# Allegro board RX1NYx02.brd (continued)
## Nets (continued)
GND_BD1: C1.2 C2.1 C3.1 C4.1 C5.1 C6.2 C7.2 C8.1 C9.1 C10.2 C13.1 C15.1 C16.2 C20.1 C145.1 C146.1 C147.1 C148.1 C149.1 C163.1 C166.2 DS_BD1_PWR.2(C) MH1.1 MH2.1 P1.2 P2.2 P3.2 P13.2 P_BD1_CLK0_N.2 P_BD1_CLK0_N.3 P_BD1_CLK0_N.4 P_BD1_CLK0_N.5 P_BD1_CLK0_N.6 P_BD1_CLK0_P.2 P_BD1_CLK0_P.3 P_BD1_CLK0_P.4 P_BD1_CLK0_P.5 P_BD1_CLK0_P.6 P_BD1_CLK1_N.2 P_BD1_CLK1_N.3 P_BD1_CLK1_N.4 P_BD1_CLK1_N.5 P_BD1_CLK1_N.6(MH6) P_BD1_CLK1_P.2 P_BD1_CLK1_P.3 P_BD1_CLK1_P.4 P_BD1_CLK1_P.5 P_BD1_CLK1_P.6(MH6) P_BD1_CLK2_N.2 P_BD1_CLK2_N.3 P_BD1_CLK2_N.4 P_BD1_CLK2_N.5 P_BD1_CLK2_N.6 P_BD1_CLK2_P.2 P_BD1_CLK2_P.3 P_BD1_CLK2_P.4 P_BD1_CLK2_P.5 P_BD1_CLK2_P.6 P_BD1_CLK3_N.2 P_BD1_CLK3_N.3 P_BD1_CLK3_N.4 P_BD1_CLK3_N.5 P_BD1_CLK3_N.6(MH6) P_BD1_CLK3_P.2 P_BD1_CLK3_P.3 P_BD1_CLK3_P.4 P_BD1_CLK3_P.5 P_BD1_CLK3_P.6(MH6) P_BD1_CMTS_N.2 P_BD1_CMTS_N.3 P_BD1_CMTS_N.4 P_BD1_CMTS_N.5 P_BD1_CMTS_N.6 P_BD1_CMTS_P.2 P_BD1_CMTS_P.3 P_BD1_CMTS_P.4 P_BD1_CMTS_P.5 P_BD1_CMTS_P.6 P_BD1_TRIG_IN_N.2 P_BD1_TRIG_IN_N.3 P_BD1_TRIG_IN_N.4 P_BD1_TRIG_IN_N.5 P_BD1_TRIG_IN_N.6(MH6) P_BD1_TRIG_IN_P.2 P_BD1_TRIG_IN_P.3 P_BD1_TRIG_IN_P.4 P_BD1_TRIG_IN_P.5 P_BD1_TRIG_IN_P.6(MH6) P_CPU_OCP_0_N.2 P_CPU_OCP_0_N.3 P_CPU_OCP_0_N.4 P_CPU_OCP_0_N.5 P_CPU_OCP_0_N.6 P_CPU_OCP_0_P.2 P_CPU_OCP_0_P.3 P_CPU_OCP_0_P.4 P_CPU_OCP_0_P.5 P_CPU_OCP_0_P.6 P_CPU_OCP_1_N.2 P_CPU_OCP_1_N.3 P_CPU_OCP_1_N.4 P_CPU_OCP_1_N.5 P_CPU_OCP_1_N.6 P_CPU_OCP_1_P.2 P_CPU_OCP_1_P.3 P_CPU_OCP_1_P.4 P_CPU_OCP_1_P.5 P_CPU_OCP_1_P.6 P_CPU_OCP_2_N.2 P_CPU_OCP_2_N.3 P_CPU_OCP_2_N.4 P_CPU_OCP_2_N.5 P_CPU_OCP_2_N.6 P_CPU_OCP_2_P.2 P_CPU_OCP_2_P.3 P_CPU_OCP_2_P.4 P_CPU_OCP_2_P.5 P_CPU_OCP_2_P.6 P_CPU_OCP_3_N.2 P_CPU_OCP_3_N.3 P_CPU_OCP_3_N.4 P_CPU_OCP_3_N.5 P_CPU_OCP_3_N.6 P_CPU_OCP_3_P.2 P_CPU_OCP_3_P.3 P_CPU_OCP_3_P.4 P_CPU_OCP_3_P.5 P_CPU_OCP_3_P.6 P_CPU_OCP_4_N.2 P_CPU_OCP_4_N.3 P_CPU_OCP_4_N.4 P_CPU_OCP_4_N.5 P_CPU_OCP_4_N.6 P_CPU_OCP_4_P.2 P_CPU_OCP_4_P.3 P_CPU_OCP_4_P.4 P_CPU_OCP_4_P.5 P_CPU_OCP_4_P.6 P_CPU_OCP_5_N.2 P_CPU_OCP_5_N.3 P_CPU_OCP_5_N.4 P_CPU_OCP_5_N.5 P_CPU_OCP_5_N.6 P_CPU_OCP_5_P.2 P_CPU_OCP_5_P.3 P_CPU_OCP_5_P.4 P_CPU_OCP_5_P.5 P_CPU_OCP_5_P.6 P_CPU_OCP_6_N.2 P_CPU_OCP_6_N.3 P_CPU_OCP_6_N.4 P_CPU_OCP_6_N.5 P_CPU_OCP_6_N.6 P_CPU_OCP_6_P.2 P_CPU_OCP_6_P.3 P_CPU_OCP_6_P.4 P_CPU_OCP_6_P.5 P_CPU_OCP_6_P.6 P_CPU_OCP_7_N.2 P_CPU_OCP_7_N.3 P_CPU_OCP_7_N.4 P_CPU_OCP_7_N.5 P_CPU_OCP_7_N.6 P_CPU_OCP_7_P.2 P_CPU_OCP_7_P.3 P_CPU_OCP_7_P.4 P_CPU_OCP_7_P.5 P_CPU_OCP_7_P.6 P_OCP1.A1 P_OCP1.A2 P_OCP1.A3 P_OCP1.A4 P_OCP1.A5 P_OCP1.A6 P_OCP1.A13 P_OCP1.A16 P_OCP1.A19 P_OCP1.A22 P_OCP1.A25 P_OCP1.A28 P_OCP1.A29 P_OCP1.A32 P_OCP1.A35 P_OCP1.A38 P_OCP1.A41 P_OCP1.A43 P_OCP1.A46 P_OCP1.A49 P_OCP1.A52 P_OCP1.A55 P_OCP1.A58 P_OCP1.A61 P_OCP1.A64 P_OCP1.A67 P_OCP1.B13 P_OCP1.B16 P_OCP1.B19 P_OCP1.B22 P_OCP1.B25 P_OCP1.B28 P_OCP1.B29 P_OCP1.B32 P_OCP1.B35 P_OCP1.B38 P_OCP1.B41 P_OCP1.B43 P_OCP1.B46 P_OCP1.B49 P_OCP1.B52 P_OCP1.B55 P_OCP1.B58 P_OCP1.B61 P_OCP1.B64 P_OCP1.B67 P_OCP1.OCP_A10 P_OCP1.OCP_A13 P_OCP1.OCP_B10 P_OCP1.OCP_B13 P_OCP_CPU_0_N.2 P_OCP_CPU_0_N.3 P_OCP_CPU_0_N.4 P_OCP_CPU_0_N.5 P_OCP_CPU_0_N.6(MH6) P_OCP_CPU_0_P.2 P_OCP_CPU_0_P.3 P_OCP_CPU_0_P.4 P_OCP_CPU_0_P.5 P_OCP_CPU_0_P.6(MH6) P_OCP_CPU_1_N.2 P_OCP_CPU_1_N.3 P_OCP_CPU_1_N.4 P_OCP_CPU_1_N.5 P_OCP_CPU_1_N.6(MH6) P_OCP_CPU_1_P.2 P_OCP_CPU_1_P.3 P_OCP_CPU_1_P.4 P_OCP_CPU_1_P.5 P_OCP_CPU_1_P.6(MH6) P_OCP_CPU_2_N.2 P_OCP_CPU_2_N.3 P_OCP_CPU_2_N.4 P_OCP_CPU_2_N.5 P_OCP_CPU_2_N.6(MH6) P_OCP_CPU_2_P.2 P_OCP_CPU_2_P.3 P_OCP_CPU_2_P.4 P_OCP_CPU_2_P.5 P_OCP_CPU_2_P.6(MH6) P_OCP_CPU_3_N.2 P_OCP_CPU_3_N.3 P_OCP_CPU_3_N.4 P_OCP_CPU_3_N.5 P_OCP_CPU_3_N.6(MH6) P_OCP_CPU_3_P.2 P_OCP_CPU_3_P.3 P_OCP_CPU_3_P.4 P_OCP_CPU_3_P.5 P_OCP_CPU_3_P.6(MH6) P_OCP_CPU_4_N.2 P_OCP_CPU_4_N.3 P_OCP_CPU_4_N.4 P_OCP_CPU_4_N.5 P_OCP_CPU_4_N.6(MH6) P_OCP_CPU_4_P.2 P_OCP_CPU_4_P.3 P_OCP_CPU_4_P.4 P_OCP_CPU_4_P.5 P_OCP_CPU_4_P.6(MH6) P_OCP_CPU_5_N.2 P_OCP_CPU_5_N.3 P_OCP_CPU_5_N.4 P_OCP_CPU_5_N.5 P_OCP_CPU_5_N.6(MH6) P_OCP_CPU_5_P.2 P_OCP_CPU_5_P.3 P_OCP_CPU_5_P.4 P_OCP_CPU_5_P.5 P_OCP_CPU_5_P.6(MH6) P_OCP_CPU_6_N.2 P_OCP_CPU_6_N.3 P_OCP_CPU_6_N.4 P_OCP_CPU_6_N.5 P_OCP_CPU_6_N.6(MH6) P_OCP_CPU_6_P.2 P_OCP_CPU_6_P.3 P_OCP_CPU_6_P.4 P_OCP_CPU_6_P.5 P_OCP_CPU_6_P.6(MH6) P_OCP_CPU_7_N.2 P_OCP_CPU_7_N.3 P_OCP_CPU_7_N.4 P_OCP_CPU_7_N.5 P_OCP_CPU_7_N.6(MH6) P_OCP_CPU_7_P.2 P_OCP_CPU_7_P.3 P_OCP_CPU_7_P.4 P_OCP_CPU_7_P.5 P_OCP_CPU_7_P.6(MH6) Q1.2(S) SW1.2 U1.3 U2.3 U3.3 U4.1 U5.3 U6.3 U7.3 U24.9 U24.17 U26.3
GND_BD2: BD2_P_OCP_CPU_0_N.2 BD2_P_OCP_CPU_0_N.3 BD2_P_OCP_CPU_0_N.4 BD2_P_OCP_CPU_0_N.5 BD2_P_OCP_CPU_0_N.6(MH6) BD2_P_OCP_CPU_0_P.2 BD2_P_OCP_CPU_0_P.3 BD2_P_OCP_CPU_0_P.4 BD2_P_OCP_CPU_0_P.5 BD2_P_OCP_CPU_0_P.6(MH6) C73.2 C74.1 C75.2 C76.1 C77.1 C78.1 C79.1 C80.2 C81.2 C82.1 C83.1 C84.2 C85.2 C87.1 C88.2 C89.1 C155.1 C156.1 C158.1 C165.1 C167.2 DS_BD2_PWR.2(C) MH5.1 MH6.1 P7.2 P8.2 P9.2 P15.2 P_BD2_CLK0_N.2 P_BD2_CLK0_N.3 P_BD2_CLK0_N.4 P_BD2_CLK0_N.5 P_BD2_CLK0_N.6 P_BD2_CLK0_P.2 P_BD2_CLK0_P.3 P_BD2_CLK0_P.4 P_BD2_CLK0_P.5 P_BD2_CLK0_P.6 P_BD2_CLK1_N.2 P_BD2_CLK1_N.3 P_BD2_CLK1_N.4 P_BD2_CLK1_N.5 P_BD2_CLK1_N.6(MH6) P_BD2_CLK1_P.2 P_BD2_CLK1_P.3 P_BD2_CLK1_P.4 P_BD2_CLK1_P.5 P_BD2_CLK1_P.6(MH6) P_BD2_CLK2_N.2 P_BD2_CLK2_N.3 P_BD2_CLK2_N.4 P_BD2_CLK2_N.5 P_BD2_CLK2_N.6 P_BD2_CLK2_P.2 P_BD2_CLK2_P.3 P_BD2_CLK2_P.4 P_BD2_CLK2_P.5 P_BD2_CLK2_P.6 P_BD2_CMTS_N.2 P_BD2_CMTS_N.3 P_BD2_CMTS_N.4 P_BD2_CMTS_N.5 P_BD2_CMTS_N.6 P_BD2_CMTS_P.2 P_BD2_CMTS_P.3 P_BD2_CMTS_P.4 P_BD2_CMTS_P.5 P_BD2_CMTS_P.6 P_BD2_TRIG_IN_N.2 P_BD2_TRIG_IN_N.3 P_BD2_TRIG_IN_N.4 P_BD2_TRIG_IN_N.5 P_BD2_TRIG_IN_N.6(MH6) P_BD2_TRIG_IN_P.2 P_BD2_TRIG_IN_P.3 P_BD2_TRIG_IN_P.4 P_BD2_TRIG_IN_P.5 P_BD2_TRIG_IN_P.6(MH6) P_CPU_OCP_8_N.2 P_CPU_OCP_8_N.3 P_CPU_OCP_8_N.4 P_CPU_OCP_8_N.5 P_CPU_OCP_8_N.6 P_CPU_OCP_8_P.2 P_CPU_OCP_8_P.3 P_CPU_OCP_8_P.4 P_CPU_OCP_8_P.5 P_CPU_OCP_8_P.6 P_CPU_OCP_9_N.2 P_CPU_OCP_9_N.3 P_CPU_OCP_9_N.4 P_CPU_OCP_9_N.5 P_CPU_OCP_9_N.6 P_CPU_OCP_9_P.2 P_CPU_OCP_9_P.3 P_CPU_OCP_9_P.4 P_CPU_OCP_9_P.5 P_CPU_OCP_9_P.6 P_CPU_OCP_10_N.2 P_CPU_OCP_10_N.3 P_CPU_OCP_10_N.4 P_CPU_OCP_10_N.5 P_CPU_OCP_10_N.6 P_CPU_OCP_10_P.2 P_CPU_OCP_10_P.3 P_CPU_OCP_10_P.4 P_CPU_OCP_10_P.5 P_CPU_OCP_10_P.6 P_CPU_OCP_11_N.2 P_CPU_OCP_11_N.3 P_CPU_OCP_11_N.4 P_CPU_OCP_11_N.5 P_CPU_OCP_11_N.6 P_CPU_OCP_11_P.2 P_CPU_OCP_11_P.3 P_CPU_OCP_11_P.4 P_CPU_OCP_11_P.5 P_CPU_OCP_11_P.6 P_CPU_OCP_12_N.2 P_CPU_OCP_12_N.3 P_CPU_OCP_12_N.4 P_CPU_OCP_12_N.5 P_CPU_OCP_12_N.6 P_CPU_OCP_12_P.2 P_CPU_OCP_12_P.3 P_CPU_OCP_12_P.4 P_CPU_OCP_12_P.5 P_CPU_OCP_12_P.6 P_CPU_OCP_13_N.2 P_CPU_OCP_13_N.3 P_CPU_OCP_13_N.4 P_CPU_OCP_13_N.5 P_CPU_OCP_13_N.6 P_CPU_OCP_13_P.2 P_CPU_OCP_13_P.3 P_CPU_OCP_13_P.4 P_CPU_OCP_13_P.5 P_CPU_OCP_13_P.6 P_CPU_OCP_14_N.2 P_CPU_OCP_14_N.3 P_CPU_OCP_14_N.4 P_CPU_OCP_14_N.5 P_CPU_OCP_14_N.6 P_CPU_OCP_14_P.2 P_CPU_OCP_14_P.3 P_CPU_OCP_14_P.4 P_CPU_OCP_14_P.5 P_CPU_OCP_14_P.6 P_CPU_OCP_15_N.2 P_CPU_OCP_15_N.3 P_CPU_OCP_15_N.4 P_CPU_OCP_15_N.5 P_CPU_OCP_15_N.6 P_CPU_OCP_15_P.2 P_CPU_OCP_15_P.3 P_CPU_OCP_15_P.4 P_CPU_OCP_15_P.5 P_CPU_OCP_15_P.6 P_OCP2.A1 P_OCP2.A2 P_OCP2.A3 P_OCP2.A4 P_OCP2.A5 P_OCP2.A6 P_OCP2.A13 P_OCP2.A16 P_OCP2.A19 P_OCP2.A22 P_OCP2.A25 P_OCP2.A28 P_OCP2.A29 P_OCP2.A32 P_OCP2.A35 P_OCP2.A38 P_OCP2.A41 P_OCP2.A43 P_OCP2.A46 P_OCP2.A49 P_OCP2.A52 P_OCP2.A55 P_OCP2.A58 P_OCP2.A61 P_OCP2.A64 P_OCP2.A67 P_OCP2.B13 P_OCP2.B16 P_OCP2.B19 P_OCP2.B22 P_OCP2.B25 P_OCP2.B28 P_OCP2.B29 P_OCP2.B32 P_OCP2.B35 P_OCP2.B38 P_OCP2.B41 P_OCP2.B43 P_OCP2.B46 P_OCP2.B49 P_OCP2.B52 P_OCP2.B55 P_OCP2.B58 P_OCP2.B61 P_OCP2.B64 P_OCP2.B67 P_OCP2.OCP_A10 P_OCP2.OCP_A13 P_OCP2.OCP_B10 P_OCP2.OCP_B13 P_OCP_CPU_8_N.2 P_OCP_CPU_8_N.3 P_OCP_CPU_8_N.4 P_OCP_CPU_8_N.5 P_OCP_CPU_8_N.6(MH6) P_OCP_CPU_8_P.2 P_OCP_CPU_8_P.3 P_OCP_CPU_8_P.4 P_OCP_CPU_8_P.5 P_OCP_CPU_8_P.6(MH6) P_OCP_CPU_9_N.2 P_OCP_CPU_9_N.3 P_OCP_CPU_9_N.4 P_OCP_CPU_9_N.5 P_OCP_CPU_9_N.6(MH6) P_OCP_CPU_9_P.2 P_OCP_CPU_9_P.3 P_OCP_CPU_9_P.4 P_OCP_CPU_9_P.5 P_OCP_CPU_9_P.6(MH6) P_OCP_CPU_10_N.2 P_OCP_CPU_10_N.3 P_OCP_CPU_10_N.4 P_OCP_CPU_10_N.5 P_OCP_CPU_10_N.6(MH6) P_OCP_CPU_10_P.2 P_OCP_CPU_10_P.3 P_OCP_CPU_10_P.4 P_OCP_CPU_10_P.5 P_OCP_CPU_10_P.6(MH6) P_OCP_CPU_11_N.2 P_OCP_CPU_11_N.3 P_OCP_CPU_11_N.4 P_OCP_CPU_11_N.5 P_OCP_CPU_11_N.6(MH6) P_OCP_CPU_11_P.2 P_OCP_CPU_11_P.3 P_OCP_CPU_11_P.4 P_OCP_CPU_11_P.5 P_OCP_CPU_11_P.6(MH6) P_OCP_CPU_12_N.2 P_OCP_CPU_12_N.3 P_OCP_CPU_12_N.4 P_OCP_CPU_12_N.5 P_OCP_CPU_12_N.6(MH6) P_OCP_CPU_12_P.2 P_OCP_CPU_12_P.3 P_OCP_CPU_12_P.4 P_OCP_CPU_12_P.5 P_OCP_CPU_12_P.6(MH6) P_OCP_CPU_13_N.2 P_OCP_CPU_13_N.3 P_OCP_CPU_13_N.4 P_OCP_CPU_13_N.5 P_OCP_CPU_13_N.6(MH6) P_OCP_CPU_13_P.2 P_OCP_CPU_13_P.3 P_OCP_CPU_13_P.4 P_OCP_CPU_13_P.5 P_OCP_CPU_13_P.6(MH6) P_OCP_CPU_14_N.2 P_OCP_CPU_14_N.3 P_OCP_CPU_14_N.4 P_OCP_CPU_14_N.5 P_OCP_CPU_14_N.6(MH6) P_OCP_CPU_14_P.2 P_OCP_CPU_14_P.3 P_OCP_CPU_14_P.4 P_OCP_CPU_14_P.5 P_OCP_CPU_14_P.6(MH6) P_OCP_CPU_15_N.2 P_OCP_CPU_15_N.3 P_OCP_CPU_15_N.4 P_OCP_CPU_15_N.5 P_OCP_CPU_15_N.6(MH6) P_OCP_CPU_15_P.2 P_OCP_CPU_15_P.3 P_OCP_CPU_15_P.4 P_OCP_CPU_15_P.5 P_OCP_CPU_15_P.6(MH6) Q3.2(S) SW3.2 U17.3 U18.3 U19.3 U20.1 U21.3 U22.3 U23.3 U25.9 U25.17 U27.3
GND_SIGNAL: J_S2D_BOT.1(GND) J_S2D_TOP.1(GND) Z_42.5_BOT.1 Z_42.5_BOT.3(RY) Z_42.5_BOT_END.1 Z_42.5_BOT_END.3 Z_42.5_TOP.1 Z_42.5_TOP.3(RY) Z_42.5_TOP_END.1 Z_42.5_TOP_END.3 Z_85D_BOT.1 Z_85D_BOT.3(RY) Z_85D_BOT_END.1 Z_85D_BOT_END.4 Z_85D_TOP.1 Z_85D_TOP.3(RY) Z_85D_TOP_END.1 Z_85D_TOP_END.4 Z_100D_BOT.1 Z_100D_BOT.3(RY) Z_100D_BOT_END.1 Z_100D_BOT_END.4 Z_100D_TOP.1 Z_100D_TOP.3(RY) Z_100D_TOP_END.1 Z_100D_TOP_END.4
BD1_555_DISCHARGE: C6.1 R11.1 R13.1 U4.6 U4.7
BD1_555_OUT: R16.2 R18.2 U4.3
BD1_555_OUT_JP: P3.1 R16.1
BD1_555_RST_N: C7.1 R15.1 U4.4
BD1_555_TRI: R8.2 R14.2 U4.2
BD1_AUX_PWR_EN: P_OCP1.B12 TP26.TEST
BD1_BIF0_N: P_OCP1.B7 TP18.TEST
BD1_BIF1_N: P_OCP1.B8 TP20.TEST
BD1_BIF2_N: P_OCP1.B9 TP22.TEST
BD1_BTN_NC: R7.1 R9.1 SW1.1 U1.1
BD1_BTN_NO: R8.1 R17.1 SW1.3 U6.2
BD1_BUS_SEL: C163.2 P13.1 Q1.1 R7.2 R18.1 R158.1 U26.2
BD1_CLK_NCSI: P_OCP1.OCP_A14 TP17.TEST
BD1_MAIN_PWR_EN: P_OCP1.OCP_B2 TP27.TEST
BD1_NCSI_ARBIN: P_OCP1.OCP_A4 TP8.TEST
BD1_NCSI_ARBOUT: P_OCP1.OCP_A5 TP9.TEST
BD1_NCSI_CRS_DV: P_OCP1.OCP_B14 TP16.TEST
BD1_NCSI_RXD0: P_OCP1.OCP_B9 TP14.TEST
BD1_NCSI_RXD1: P_OCP1.OCP_B8 TP12.TEST
BD1_NCSI_TXD0: P_OCP1.OCP_A9 TP15.TEST
BD1_NCSI_TXD1: P_OCP1.OCP_A8 TP13.TEST
BD1_NCSI_TXEN: P_OCP1.OCP_A7 TP11.TEST
BD1_NIC_PWR_GOOD: P_OCP1.OCP_B1 R5.1
BD1_PERST0_N: P_OCP1.B10 TP24.TEST
BD1_PERST1_N: P_OCP1.A11 TP25.TEST
BD1_PERST2_N: P_OCP1.OCP_A1 TP3.TEST
BD1_PERST3_N: P_OCP1.OCP_A2 TP4.TEST
BD1_PRSNTA_N: P_OCP1.A10 R1.2 R2.2 R3.2 R6.2
BD1_PRSNTB0_N: P_OCP1.B42 R1.1
BD1_PRSNTB1_N: P_OCP1.A42 R2.1
BD1_PRSNTB2_N: P_OCP1.A12 R3.1
BD1_PRSNTB3_N: P_OCP1.B70 R6.1
BD1_PWRBRK_N: P_OCP1.A70 R164.1
BD1_REFCLK0_DN: P_BD1_CLK0_N.1 P_OCP1.B14
BD1_REFCLK0_DP: P_BD1_CLK0_P.1 P_OCP1.B15
BD1_REFCLK1_DN: P_BD1_CLK1_N.1 P_OCP1.A14
BD1_REFCLK1_DP: P_BD1_CLK1_P.1 P_OCP1.A15
BD1_REFCLK2_DN: P_BD1_CLK2_N.1 P_OCP1.OCP_B11
BD1_REFCLK2_DP: P_BD1_CLK2_P.1 P_OCP1.OCP_B12
BD1_REFCLK3_DN: P_BD1_CLK3_N.1 P_OCP1.OCP_A11
BD1_REFCLK3_DP: P_BD1_CLK3_P.1 P_OCP1.OCP_A12
BD1_SCAN_CLK: P_OCP1.OCP_B6 TP1.TEST
BD1_SCAN_DATA_IN: P_OCP1.OCP_B4 TP7.TEST
BD1_SCAN_DATA_OUT: P_OCP1.OCP_B5 TP10.TEST
BD1_SCAN_LD_N: P_OCP1.OCP_B3 TP5.TEST
BD1_SLOT_ID: P_OCP1.OCP_B7 TP2.TEST
BD1_SMB_CLK: P_OCP1.A7 TP19.TEST
BD1_SMB_RST_N: P_OCP1.A9 TP23.TEST
BD1_SMB_SDA: P_OCP1.A8 TP21.TEST
BD1_WAKE_N: P_OCP1.OCP_A3 TP6.TEST
BD2_555_DISCHARGE: C80.1 R88.1 R89.1 U20.6 U20.7
BD2_555_OUT: R93.2 R95.2 U20.3
BD2_555_OUT_JP: P9.1 R93.1
BD2_555_RST_N: C81.1 R92.1 U20.4
BD2_555_TRI: R85.2 R91.2 U20.2
BD2_AUX_PWR_EN: P_OCP2.B12 TP81.TEST
BD2_BIF0_N: P_OCP2.B7 TP72.TEST
BD2_BIF1_N: P_OCP2.B8 TP73.TEST
BD2_BIF2_N: P_OCP2.B9 TP77.TEST
BD2_BTN_NC: R84.1 R86.1 SW3.1 U17.1
BD2_BTN_NO: R85.1 R94.1 SW3.3 U22.2
BD2_BUS_SEL: C165.2 P15.1 Q3.1 R84.2 R95.1 R160.1 U27.2
BD2_CLK_NCSI: P_OCP2.OCP_A14 TP71.TEST
BD2_MAIN_PWR_EN: P_OCP2.OCP_B2 TP56.TEST
BD2_NCSI_ARBIN: P_OCP2.OCP_A4 TP74.TEST
BD2_NCSI_ARBOUT: P_OCP2.OCP_A5 TP62.TEST
BD2_NCSI_CRS_DV: P_OCP2.OCP_B14 TP70.TEST
BD2_NCSI_RXD0: P_OCP2.OCP_B9 TP68.TEST
BD2_NCSI_RXD1: P_OCP2.OCP_B8 TP66.TEST
BD2_NCSI_TXD0: P_OCP2.OCP_A9 TP69.TEST
BD2_NCSI_TXD1: P_OCP2.OCP_A8 TP67.TEST
BD2_NCSI_TXEN: P_OCP2.OCP_A7 TP65.TEST
BD2_NIC_PWR_GOOD: P_OCP2.OCP_B1 R79.1
BD2_PE_OCP_CPU_0_DN: BD2_P_OCP_CPU_0_N.1 P_OCP2.A17
BD2_PE_OCP_CPU_0_DP: BD2_P_OCP_CPU_0_P.1 P_OCP2.A18
BD2_PERST0_N: P_OCP2.B10 TP79.TEST
BD2_PERST1_N: P_OCP2.A11 TP80.TEST
BD2_PERST2_N: P_OCP2.OCP_A1 TP55.TEST
BD2_PERST3_N: P_OCP2.OCP_A2 TP57.TEST
BD2_PRSNTA_N: P_OCP2.A10 R78.2 R80.2 R81.2 R82.2
BD2_PRSNTB0_N: P_OCP2.B42 R78.1
BD2_PRSNTB1_N: P_OCP2.A42 R80.1
BD2_PRSNTB2_N: P_OCP2.A12 R81.1
BD2_PRSNTB3_N: P_OCP2.B70 R82.1
BD2_PWRBRK_N: P_OCP2.A70 R166.1
BD2_REFCLK0_DN: P_BD2_CLK0_N.1 P_OCP2.B14
BD2_REFCLK0_DP: P_BD2_CLK0_P.1 P_OCP2.B15
BD2_REFCLK1_DN: P_BD2_CLK1_N.1 P_OCP2.A14
BD2_REFCLK1_DP: P_BD2_CLK1_P.1 P_OCP2.A15
BD2_REFCLK2_DN: P_BD2_CLK2_N.1 P_OCP2.OCP_B11
BD2_REFCLK2_DP: P_BD2_CLK2_P.1 P_OCP2.OCP_B12
BD2_REFCLK3_DN: P_OCP2.OCP_A11 TP82.TEST
BD2_REFCLK3_DP: P_OCP2.OCP_A12 TP83.TEST
BD2_SCAN_CLK: P_OCP2.OCP_B6 TP63.TEST
BD2_SCAN_DATA_IN: P_OCP2.OCP_B4 TP60.TEST
BD2_SCAN_DATA_OUT: P_OCP2.OCP_B5 TP61.TEST
BD2_SCAN_LD_N: P_OCP2.OCP_B3 TP58.TEST
BD2_SLOT_ID: P_OCP2.OCP_B7 TP64.TEST
BD2_SLOT_ID1: P_OCP2.OCP_A6
BD2_SMB_CLK: P_OCP2.A7 TP75.TEST
BD2_SMB_RST_N: P_OCP2.A9 TP78.TEST
BD2_SMB_SDA: P_OCP2.A8 TP76.TEST
BD2_WAKE_N: P_OCP2.OCP_A3 TP59.TEST
CLK1_HOST_TO_TRIGGER_DN: C149.2 P_BD1_TRIG_IN_N.1 U24.2
CLK1_HOST_TO_TRIGGER_DP: C148.2 P_BD1_TRIG_IN_P.1 U24.1
CLK1_TRIG_SIGNAL_C_DN: C12.1 R21.1
CLK1_TRIG_SIGNAL_C_DP: C11.1 R19.1
CLK1_TRIG_SIGNAL_DN: C12.2 U24.11
CLK1_TRIG_SIGNAL_DP: C11.2 U24.10
CLK1_TRIG_SIGNAL_R_DN: P_BD1_CMTS_N.1 R21.2
CLK1_TRIG_SIGNAL_R_DP: P_BD1_CMTS_P.1 R19.2
CLK2_HOST_TO_TRIGGER_DN: C158.2 P_BD2_TRIG_IN_N.1 U25.2
CLK2_HOST_TO_TRIGGER_DP: C156.2 P_BD2_TRIG_IN_P.1 U25.1
CLK2_TRIG_SIGNAL_C_DN: C90.1 R99.1
CLK2_TRIG_SIGNAL_C_DP: C86.1 R96.1
CLK2_TRIG_SIGNAL_DN: C90.2 U25.11
CLK2_TRIG_SIGNAL_DP: C86.2 U25.10
CLK2_TRIG_SIGNAL_R_DN: P_BD2_CMTS_N.1 R99.2
CLK2_TRIG_SIGNAL_R_DP: P_BD2_CMTS_P.1 R96.2
NC1_A6_SLOT_ID1: P_OCP1.OCP_A6
NC1_A68: P_OCP1.A68
NC1_A69: P_OCP1.A69
NC1_B68: P_OCP1.B68
NC1_B69: P_OCP1.B69
NC2_A68: P_OCP2.A68
NC2_A69: P_OCP2.A69
NC2_B68: P_OCP2.B68
NC2_B69: P_OCP2.B69
PE_CAL_BOT_OCP_CPU_0_DN: P_CAL_OCP_CPU_B_0_N.1 P_OCPSTRDL.A17
PE_CAL_BOT_OCP_CPU_0_DP: P_CAL_OCP_CPU_B_0_P.1 P_OCPSTRDL.A18
PE_CAL_CPU_OCP_0_DN: P_CAL_CPU_OCP_0_N1.1 P_OCPSTRDL.B17
PE_CAL_CPU_OCP_0_DP: P_CAL_CPU_OCP_0_P1.1 P_OCPSTRDL.B18
PE_CPU_OCP_0_DN: P_CPU_OCP_0_N.1 P_OCP1.B17
PE_CPU_OCP_0_DP: P_CPU_OCP_0_P.1 P_OCP1.B18
PE_CPU_OCP_1_DN: P_CPU_OCP_1_N.1 P_OCP1.B20
PE_CPU_OCP_1_DP: P_CPU_OCP_1_P.1 P_OCP1.B21
PE_CPU_OCP_2_DN: P_CPU_OCP_2_N.1 P_OCP1.B23
PE_CPU_OCP_2_DP: P_CPU_OCP_2_P.1 P_OCP1.B24
PE_CPU_OCP_3_DN: P_CPU_OCP_3_N.1 P_OCP1.B26
PE_CPU_OCP_3_DP: P_CPU_OCP_3_P.1 P_OCP1.B27
PE_CPU_OCP_4_DN: P_CPU_OCP_4_N.1 P_OCP1.B30
PE_CPU_OCP_4_DP: P_CPU_OCP_4_P.1 P_OCP1.B31
PE_CPU_OCP_5_DN: P_CPU_OCP_5_N.1 P_OCP1.B33
PE_CPU_OCP_5_DP: P_CPU_OCP_5_P.1 P_OCP1.B34
PE_CPU_OCP_6_DN: P_CPU_OCP_6_N.1 P_OCP1.B36
PE_CPU_OCP_6_DP: P_CPU_OCP_6_P.1 P_OCP1.B37
PE_CPU_OCP_7_DN: P_CPU_OCP_7_N.1 P_OCP1.B39
PE_CPU_OCP_7_DP: P_CPU_OCP_7_P.1 P_OCP1.B40
PE_CPU_OCP_8_DN: P_CPU_OCP_8_N.1 P_OCP2.B44
PE_CPU_OCP_8_DP: P_CPU_OCP_8_P.1 P_OCP2.B45
PE_CPU_OCP_9_DN: P_CPU_OCP_9_N.1 P_OCP2.B47
PE_CPU_OCP_9_DP: P_CPU_OCP_9_P.1 P_OCP2.B48
PE_CPU_OCP_10_DN: P_CPU_OCP_10_N.1 P_OCP2.B50
PE_CPU_OCP_10_DP: P_CPU_OCP_10_P.1 P_OCP2.B51
PE_CPU_OCP_11_DN: P_CPU_OCP_11_N.1 P_OCP2.B53
PE_CPU_OCP_11_DP: P_CPU_OCP_11_P.1 P_OCP2.B54
PE_CPU_OCP_12_DN: P_CPU_OCP_12_N.1 P_OCP2.B56
PE_CPU_OCP_12_DP: P_CPU_OCP_12_P.1 P_OCP2.B57
PE_CPU_OCP_13_DN: P_CPU_OCP_13_N.1 P_OCP2.B59
PE_CPU_OCP_13_DP: P_CPU_OCP_13_P.1 P_OCP2.B60
PE_CPU_OCP_14_DN: P_CPU_OCP_14_N.1 P_OCP2.B62
PE_CPU_OCP_14_DP: P_CPU_OCP_14_P.1 P_OCP2.B63
PE_CPU_OCP_15_DN: P_CPU_OCP_15_N.1 P_OCP2.B65
PE_CPU_OCP_15_DP: P_CPU_OCP_15_P.1 P_OCP2.B66
PE_OCP_CPU_0_DN: P_OCP1.A17 P_OCP_CPU_0_N.1
PE_OCP_CPU_0_DP: P_OCP1.A18 P_OCP_CPU_0_P.1
PE_OCP_CPU_1_DN: P_OCP1.A20 P_OCP_CPU_1_N.1
PE_OCP_CPU_1_DP: P_OCP1.A21 P_OCP_CPU_1_P.1
PE_OCP_CPU_2_DN: P_OCP1.A23 P_OCP_CPU_2_N.1
PE_OCP_CPU_2_DP: P_OCP1.A24 P_OCP_CPU_2_P.1
PE_OCP_CPU_3_DN: P_OCP1.A26 P_OCP_CPU_3_N.1
PE_OCP_CPU_3_DP: P_OCP1.A27 P_OCP_CPU_3_P.1
PE_OCP_CPU_4_DN: P_OCP1.A30 P_OCP_CPU_4_N.1
PE_OCP_CPU_4_DP: P_OCP1.A31 P_OCP_CPU_4_P.1
PE_OCP_CPU_5_DN: P_OCP1.A33 P_OCP_CPU_5_N.1
PE_OCP_CPU_5_DP: P_OCP1.A34 P_OCP_CPU_5_P.1
PE_OCP_CPU_6_DN: P_OCP1.A36 P_OCP_CPU_6_N.1
PE_OCP_CPU_6_DP: P_OCP1.A37 P_OCP_CPU_6_P.1
PE_OCP_CPU_7_DN: P_OCP1.A39 P_OCP_CPU_7_N.1
PE_OCP_CPU_7_DP: P_OCP1.A40 P_OCP_CPU_7_P.1
PE_OCP_CPU_8_DN: P_OCP2.A44 P_OCP_CPU_8_N.1
PE_OCP_CPU_8_DP: P_OCP2.A45 P_OCP_CPU_8_P.1
PE_OCP_CPU_9_DN: P_OCP2.A47 P_OCP_CPU_9_N.1
PE_OCP_CPU_9_DP: P_OCP2.A48 P_OCP_CPU_9_P.1
PE_OCP_CPU_10_DN: P_OCP2.A50 P_OCP_CPU_10_N.1
PE_OCP_CPU_10_DP: P_OCP2.A51 P_OCP_CPU_10_P.1
PE_OCP_CPU_11_DN: P_OCP2.A53 P_OCP_CPU_11_N.1
PE_OCP_CPU_11_DP: P_OCP2.A54 P_OCP_CPU_11_P.1
PE_OCP_CPU_12_DN: P_OCP2.A56 P_OCP_CPU_12_N.1
PE_OCP_CPU_12_DP: P_OCP2.A57 P_OCP_CPU_12_P.1
PE_OCP_CPU_13_DN: P_OCP2.A59 P_OCP_CPU_13_N.1
PE_OCP_CPU_13_DP: P_OCP2.A60 P_OCP_CPU_13_P.1
PE_OCP_CPU_14_DN: P_OCP2.A62 P_OCP_CPU_14_N.1
PE_OCP_CPU_14_DP: P_OCP2.A63 P_OCP_CPU_14_P.1
PE_OCP_CPU_15_DN: P_OCP2.A65 P_OCP_CPU_15_N.1
PE_OCP_CPU_15_DP: P_OCP2.A66 P_OCP_CPU_15_P.1
SET2DIL_85_BOT: J_S2D_BOT.2 J_S2D_BOT.3
SET2DIL_85_TOP: J_S2D_TOP.2 J_S2D_TOP.3
SMA_2IN_BOT_DN: P_SMA_BOT_2IN_DN_1.1 P_SMA_BOT_2IN_DN_2.1
SMA_2IN_BOT_DP: P_SMA_BOT_2IN_DP_1.1 P_SMA_BOT_2IN_DP_2.1
SMA_2IN_TOP_DN: P_SMA_TOP_2IN_DN_1.1 P_SMA_TOP_2IN_DN_2.1
SMA_2IN_TOP_DP: P_SMA_TOP_2IN_DP_1.1 P_SMA_TOP_2IN_DP_2.1
SMA_5IN_BOT_DN: P_SMA_BOT_5IN_DN_1.1 P_SMA_BOT_5IN_DN_2.1
SMA_5IN_BOT_DP: P_SMA_BOT_5IN_DP_1.1 P_SMA_BOT_5IN_DP_2.1
SMA_5IN_TOP_DN: P_SMA_TOP_5IN_DN_1.1 P_SMA_TOP_5IN_DN_2.1
SMA_5IN_TOP_DP: P_SMA_TOP_5IN_DP_1.1 P_SMA_TOP_5IN_DP_2.1
SMA_10IN_BOT_DN: P_SMA_BOT_10IN_DN_1.1 P_SMA_BOT_10IN_DN_2.1
SMA_10IN_BOT_DP: P_SMA_BOT_10IN_DP_1.1 P_SMA_BOT_10IN_DP_2.1
SMA_10IN_TOP_DN: P_SMA_TOP_10IN_DN_1.1 P_SMA_TOP_10IN_DN_2.1
SMA_10IN_TOP_DP: P_SMA_TOP_10IN_DP_1.1 P_SMA_TOP_10IN_DP_2.1
V_3P3AUX_1: C1.1 C2.2 C3.2 C4.2 C5.2 C8.2 C9.2 C13.2 C15.2 C16.1 C20.2 C146.2 C147.2 C166.1 P_OCP1.B11 R5.2 R9.2 R11.2 R13.2 R15.2 R17.2 R20.1 R158.2 R164.2 R167.1 U1.5 U2.5 U3.5 U4.8(V+) U5.5 U6.5 U7.5 U24.13(VDD) U26.5
V_3P3AUX_2: C73.1 C74.2 C75.1 C76.2 C77.2 C78.2 C79.2 C82.2 C83.2 C85.1 C87.2 C88.1 C89.2 C167.1 P_OCP2.B11 R79.2 R86.2 R88.2 R89.2 R92.2 R94.2 R97.1 R160.2 R166.2 R168.1 U17.5 U18.5 U19.5 U20.8(V+) U21.5 U22.5 U23.5 U25.13(VDD) U27.5
V_12V_1: C145.2 C150.2 P_OCP1.B1 P_OCP1.B2 P_OCP1.B3 P_OCP1.B4 P_OCP1.B5 P_OCP1.B6 R154.2
V_12V_2: C155.2 C157.2 P_OCP2.B1 P_OCP2.B2 P_OCP2.B3 P_OCP2.B4 P_OCP2.B5 P_OCP2.B6 R156.2
Z_42.5_BOT: Z_42.5_BOT.2 Z_42.5_BOT_END.2
Z_42.5_TOP: Z_42.5_TOP.2 Z_42.5_TOP_END.2
Z_85D_BOT_DN: Z_85D_BOT.4 Z_85D_BOT_END.3
Z_85D_BOT_DP: Z_85D_BOT.2 Z_85D_BOT_END.2
Z_85D_TOP_DN: Z_85D_TOP.4 Z_85D_TOP_END.3
Z_85D_TOP_DP: Z_85D_TOP.2 Z_85D_TOP_END.2
Z_100D_BOT_DN: Z_100D_BOT.4 Z_100D_BOT_END.3
Z_100D_BOT_DP: Z_100D_BOT.2 Z_100D_BOT_END.2
Z_100D_TOP_DN: Z_100D_TOP.4 Z_100D_TOP_END.3
Z_100D_TOP_DP: Z_100D_TOP.2 Z_100D_TOP_END.2
N16712697: R12.1 U1.4(Y) U2.1 U3.1 U5.1 U5.2 U6.1
N16712704: P2.1 R12.2
N16712845: U1.2 U6.4(Y)
N16713263: U2.4(Y) U3.2 U7.1
N16713357: U2.2 U7.4(Y)
N16713385: C10.1 U5.4(Y) U7.2
N16713764: R10.1 R14.1 U3.4(Y)
N16713990: P1.1 R10.2
N16720108: DS_BD1_PWR.1 R20.2
N16815513: R90.1 U17.4(Y) U18.1 U19.1 U21.1 U21.2 U22.1
N16815530: U18.2 U19.4(Y) U23.1
N16815572: U19.2 U23.4(Y)
N16815630: C84.1 U21.4(Y) U23.2
N16815728: R87.1 R91.1 U18.4(Y)
N16815771: P7.1 R87.2
N16816367: DS_BD2_PWR.1 R97.2
N16816677: P8.1 R90.2
N16816726: U17.2 U22.4(Y)
N16866749: DS_BD1_TRIG.1 R154.1
N16866751: C150.1 DS_BD1_TRIG.2(C) Q1.3
N16879387: DS_BD2_TRIG.1 R156.1
N16879389: C157.1 DS_BD2_TRIG.2(C) Q3.3
N17127453: U24.12 U26.4(Y)
N17129452: U25.12 U27.4(Y)
N17130541: R167.2 U24.16
N17130684: R168.2 U25.16

Pads without a net: LBL1 1; LBL3 1; LBL4 1; LBL5 1; P_OCP1 A44 A45 A47 A48 A50 A51 A53 A54 A56 A57 A59 A60 A62 A63 A65 A66 B44 B45 B47 B48 B50 B51 B53 B54 B56 B57 B59 B60 B62 B63 B65 B66; P_OCP2 A20 A21 A23 A24 A26 A27 A30 A31 A33 A34 A36 A37 A39 A40 B17 B18 B20 B21 B23 B24 B26 B27 B30 B31 B33 B34 B36 B37 B39 B40; P_OCPSTRDL A7 A8 A9 A10 A11 A12 A14 A15 A20 A21 A23 A24 A26 A27 A30 A31 A33 A34 A36 A37 A39 A40 A42 A44 A45 A47 A48 A50 A51 A53 A54 A56 A57 A59 A60 A62 A63 A65 A66 A68 A69 A70 B1 B2 B3 B4 B5 B6 B7 B8 B9 B10 B11 B12 B14 B15 B20 B21 B23 B24 B26 B27 B30 B31 B33 B34 B36 B37 B39 B40 B42 B44 B45 B47 B48 B50 B51 B53 B54 B56 B57 B59 B60 B62 B63 B65 B66 B68 B69 B70 OCP_A1 OCP_A2 OCP_A3 OCP_A4 OCP_A5 OCP_A7 OCP_A8 OCP_A9 OCP_A11 OCP_A12 OCP_A14 OCP_B1 OCP_B2 OCP_B3 OCP_B4 OCP_B5 OCP_B6 OCP_B7 OCP_B8 OCP_B9 OCP_B11 OCP_B12 OCP_B14; U4 5; U20 5; U24 3 4 5 6 7 8 14 15; U25 3 4 5 6 7 8 14 15; U26 1; U27 1

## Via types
v1: diameter 0.483, hole 0.203, TOP to BOTTOM, 321 vias
v2: diameter 0.457, hole 0.203, TOP to BOTTOM, 558 vias
v3: diameter 0.254, hole 0.203, TOP to BOTTOM, 486 vias
v4: diameter 0.813, hole 0.457, TOP to BOTTOM, 28 vias
v5: diameter 0.63, hole 0.33, TOP to BOTTOM, 2 vias

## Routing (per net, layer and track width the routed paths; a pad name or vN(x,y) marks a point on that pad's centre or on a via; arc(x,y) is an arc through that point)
AGND_2: length 1480.7
  TOP w0.356: P_OCPSTRDL.A58 v1(139.9,95.81) ; P_OCPSTRDL.A49 v1(134.5,95.81) ; P_OCPSTRDL.A64 v1(143.5,95.81) ; P_OCPSTRDL.A38 v1(123.59,95.81) ; v1(106.98,95.81) v1(106.98,96.64) P_OCPSTRDL.A16 ; P_OCPSTRDL.A43 v1(130.9,95.81) ; P_OCPSTRDL.A13 v1(105.18,95.81) ; P_OCPSTRDL.A19 v1(108.78,96.64) v1(108.78,95.81) ; P_OCPSTRDL.A55 v1(138.1,95.81) ; P_OCPSTRDL.A35 v1(121.79,95.81) ; P_OCPSTRDL.A25 v1(112.38,95.81) ; P_OCPSTRDL.A32 v1(119.99,95.81) ; P_OCPSTRDL.A67 v1(145.3,95.81) ; P_OCPSTRDL.OCP_A10 v1(91.18,95.81) ; P_OCPSTRDL.A28 v1(114.18,95.81) ; P_OCPSTRDL.A61 v1(141.7,95.81) ; P_OCPSTRDL.A22 v1(110.58,95.81) ; P_OCPSTRDL.A52 v1(136.3,95.81) ; P_OCPSTRDL.OCP_A13 v1(92.98,95.81) ; P_OCPSTRDL.A46 v1(132.7,95.81) ; P_OCPSTRDL.A41 v1(125.39,95.81) ; P_OCPSTRDL.A29 v1(118.19,95.81)
  GND w0.254: P_SMA_TOP_5IN_DN_2.2 263.33,64.05 ; P_SMA_TOP_5IN_DN_2.2 263.33,62.93 ; P_SMA_TOP_5IN_DN_2.2 262.21,62.93 ; P_SMA_TOP_5IN_DN_2.2 262.21,64.05 ; P_SMA_BOT_5IN_DP_1.5 11.11,36.37 ; P_SMA_BOT_5IN_DP_1.5 9.99,36.37 ; P_SMA_BOT_5IN_DP_1.5 9.99,37.5 ; P_SMA_BOT_5IN_DP_1.5 11.11,37.5 ; 14.29,19.49 P_SMA_BOT_10IN_DN_2.5 ; P_SMA_BOT_10IN_DN_2.5 14.29,20.62 ; P_SMA_BOT_10IN_DN_2.5 15.41,20.62 ; P_SMA_BOT_10IN_DN_2.5 15.41,19.49 ; 9.99,33.02 P_SMA_BOT_5IN_DP_1.4 ; P_SMA_BOT_5IN_DP_1.4 9.99,34.15 ; P_SMA_BOT_5IN_DP_1.4 11.11,33.02 ; P_SMA_BOT_5IN_DP_1.4 11.11,34.15 ; 14.29,22.84 P_SMA_BOT_10IN_DN_2.4 ; P_SMA_BOT_10IN_DN_2.4 15.41,23.97 ; P_SMA_BOT_10IN_DN_2.4 14.29,23.97 ; P_SMA_BOT_10IN_DN_2.4 15.41,22.84 ; 34.61,23.02 P_SMA_TOP_10IN_DP_1.2 ; P_SMA_TOP_10IN_DP_1.2 35.73,23.02 ; P_SMA_TOP_10IN_DP_1.2 34.61,21.89 ; P_SMA_TOP_10IN_DP_1.2 35.73,21.89 ; P_SMA_TOP_2IN_DN_2.5 67.12,51.98 ; P_SMA_TOP_2IN_DN_2.5 67.12,50.85 ; P_SMA_TOP_2IN_DN_2.5 65.99,51.98 ; P_SMA_TOP_2IN_DN_2.5 65.99,50.85 ; P_SMA_BOT_5IN_DN_1.5 15.41,49.58 ; P_SMA_BOT_5IN_DN_1.5 15.41,48.45 ; P_SMA_BOT_5IN_DN_1.5 14.29,49.58 ; P_SMA_BOT_5IN_DN_1.5 14.29,48.45 ; P_SMA_BOT_5IN_DN_2.3 120.33,51.8 ; P_SMA_BOT_5IN_DN_2.3 119.21,52.93 ; P_SMA_BOT_5IN_DN_2.3 119.21,51.8 ; P_SMA_BOT_5IN_DN_2.3 120.33,52.93 ; 123.7,82.52 P_CAL_CPU_OCP_0_N1.5 ; P_CAL_CPU_OCP_0_N1.5 124.83,82.52 ; P_CAL_CPU_OCP_0_N1.5 124.83,81.39 ; P_CAL_CPU_OCP_0_N1.5 123.7,81.39 ; 34.61,19.67 P_SMA_TOP_10IN_DP_1.3 ; P_SMA_TOP_10IN_DP_1.3 35.73,18.54 ; P_SMA_TOP_10IN_DP_1.3 35.73,19.67 ; P_SMA_TOP_10IN_DP_1.3 34.61,18.54 ; P_CAL_CPU_OCP_0_N1.3 121.48,77.09 ; P_CAL_CPU_OCP_0_N1.3 120.35,78.22 ; P_CAL_CPU_OCP_0_N1.3 121.48,78.22 ; P_CAL_CPU_OCP_0_N1.3 120.35,77.09 ; 241.89,34.15 P_SMA_BOT_2IN_DN_2.4 ; P_SMA_BOT_2IN_DN_2.4 241.89,33.02 ; P_SMA_BOT_2IN_DN_2.4 243.01,33.02 ; P_SMA_BOT_2IN_DN_2.4 243.01,34.15 ; 136.08,81.39 P_CAL_CPU_OCP_0_P1.3 ; P_CAL_CPU_OCP_0_P1.3 137.21,82.52 ; P_CAL_CPU_OCP_0_P1.3 136.08,82.52 ; P_CAL_CPU_OCP_0_P1.3 137.21,81.39 ; P_SMA_TOP_10IN_DN_2.4 267.63,38.45 ; P_SMA_TOP_10IN_DN_2.4 266.51,37.32 ; P_SMA_TOP_10IN_DN_2.4 267.63,37.32 ; P_SMA_TOP_10IN_DN_2.4 266.51,38.45 ; P_CAL_OCP_CPU_B_0_P.2 95.76,82.52 ; P_CAL_OCP_CPU_B_0_P.2 94.63,82.52 ; P_CAL_OCP_CPU_B_0_P.2 95.76,81.39 ; P_CAL_OCP_CPU_B_0_P.2 94.63,81.39 ; P_SMA_TOP_10IN_DP_2.4 263.33,18.54 ; P_SMA_TOP_10IN_DP_2.4 262.21,18.54 ; P_SMA_TOP_10IN_DP_2.4 263.33,19.67 ; P_SMA_TOP_10IN_DP_2.4 262.21,19.67 ; P_SMA_TOP_2IN_DN_1.4 31.43,48.63 ; P_SMA_TOP_2IN_DN_1.4 30.31,47.5 ; P_SMA_TOP_2IN_DN_1.4 30.31,48.63 ; P_SMA_TOP_2IN_DN_1.4 31.43,47.5 ; 266.51,18.54 P_SMA_TOP_10IN_DP_2.3 ; P_SMA_TOP_10IN_DP_2.3 267.63,19.67 ; P_SMA_TOP_10IN_DP_2.3 266.51,19.67 ; P_SMA_TOP_10IN_DP_2.3 267.63,18.54 ; 266.51,21.89 P_SMA_TOP_10IN_DP_2.2 ; P_SMA_TOP_10IN_DP_2.2 267.63,21.89 ; P_SMA_TOP_10IN_DP_2.2 266.51,23.02 ; P_SMA_TOP_10IN_DP_2.2 267.63,23.02 ; P_SMA_TOP_5IN_DN_2.5 267.63,64.05 ; P_SMA_TOP_5IN_DN_2.5 267.63,62.93 ; P_SMA_TOP_5IN_DN_2.5 266.51,62.93 ; P_SMA_TOP_5IN_DN_2.5 266.51,64.05 ; P_SMA_BOT_10IN_DP_1.3 247.31,4.07 ; P_SMA_BOT_10IN_DP_1.3 247.31,5.19 ; P_SMA_BOT_10IN_DP_1.3 246.19,5.19 ; P_SMA_BOT_10IN_DP_1.3 246.19,4.07 ; 123.51,37.5 P_SMA_BOT_5IN_DP_2.2 ; P_SMA_BOT_5IN_DP_2.2 124.63,37.5 ; P_SMA_BOT_5IN_DP_2.2 123.51,36.37 ; P_SMA_BOT_5IN_DP_2.2 124.63,36.37 ; P_SMA_BOT_2IN_DN_1.3 211.63,33.02 ; P_SMA_BOT_2IN_DN_1.3 210.5,33.02 ; P_SMA_BOT_2IN_DN_1.3 210.5,34.15 ; P_SMA_BOT_2IN_DN_1.3 211.63,34.15 ; 85.6,81.39 P_CAL_OCP_CPU_B_0_N.5 ; P_CAL_OCP_CPU_B_0_N.5 86.73,82.52 ; P_CAL_OCP_CPU_B_0_N.5 85.6,82.52 ; P_CAL_OCP_CPU_B_0_N.5 86.73,81.39 ; P_SMA_TOP_2IN_DP_1.2 31.43,64.05 ; P_SMA_TOP_2IN_DP_1.2 30.31,62.93 ; P_SMA_TOP_2IN_DP_1.2 30.31,64.05 ; P_SMA_TOP_2IN_DP_1.2 31.43,62.93 ; 14.29,51.8 P_SMA_BOT_5IN_DN_1.4 ; P_SMA_BOT_5IN_DN_1.4 14.29,52.93 ; P_SMA_BOT_5IN_DN_1.4 15.41,52.93 ; P_SMA_BOT_5IN_DN_1.4 15.41,51.8 ; P_SMA_TOP_2IN_DP_1.3 31.43,67.4 ; P_SMA_TOP_2IN_DP_1.3 31.43,66.28 ; P_SMA_TOP_2IN_DP_1.3 30.31,66.28 ; P_SMA_TOP_2IN_DP_1.3 30.31,67.4 ; P_SMA_BOT_2IN_DN_1.5 207.33,37.5 ; P_SMA_BOT_2IN_DN_1.5 206.2,36.37 ; P_SMA_BOT_2IN_DN_1.5 207.33,36.37 ; P_SMA_BOT_2IN_DN_1.5 206.2,37.5 ; 9.99,8.54 P_SMA_BOT_10IN_DP_2.5 ; P_SMA_BOT_10IN_DP_2.5 11.11,7.42 ; P_SMA_BOT_10IN_DP_2.5 9.99,7.42 ; P_SMA_BOT_10IN_DP_2.5 11.11,8.54 ; P_SMA_TOP_5IN_DN_1.4 158.41,67.4 ; P_SMA_TOP_5IN_DN_1.4 157.29,67.4 ; P_SMA_TOP_5IN_DN_1.4 157.29,66.28 ; P_SMA_TOP_5IN_DN_1.4 158.41,66.28 ; P_SMA_BOT_2IN_DP_2.5 211.63,48.45 ; P_SMA_BOT_2IN_DP_2.5 210.5,48.45 ; P_SMA_BOT_2IN_DP_2.5 211.63,49.58 ; P_SMA_BOT_2IN_DP_2.5 210.5,49.58 ; 97.98,82.52 P_CAL_OCP_CPU_B_0_P.3 ; P_CAL_OCP_CPU_B_0_P.3 99.11,81.39 ; P_CAL_OCP_CPU_B_0_P.3 97.98,81.39 ; P_CAL_OCP_CPU_B_0_P.3 99.11,82.52 ; 241.89,4.07 P_SMA_BOT_10IN_DP_1.4 ; P_SMA_BOT_10IN_DP_1.4 243.01,4.07 ; P_SMA_BOT_10IN_DP_1.4 243.01,5.19 ; P_SMA_BOT_10IN_DP_1.4 241.89,5.19 ; P_SMA_TOP_5IN_DP_2.4 263.33,48.63 ; P_SMA_TOP_5IN_DP_2.4 262.21,48.63 ; P_SMA_TOP_5IN_DP_2.4 263.33,47.5 ; P_SMA_TOP_5IN_DP_2.4 262.21,47.5 ; P_SMA_BOT_10IN_DN_1.5 247.31,19.49 ; P_SMA_BOT_10IN_DN_1.5 246.19,19.49 ; P_SMA_BOT_10IN_DN_1.5 247.31,20.62 ; P_SMA_BOT_10IN_DN_1.5 246.19,20.62 ; 30.31,37.32 P_SMA_TOP_10IN_DN_1.3 ; P_SMA_TOP_10IN_DN_1.3 31.43,38.45 ; P_SMA_TOP_10IN_DN_1.3 30.31,38.45 ; P_SMA_TOP_10IN_DN_1.3 31.43,37.32 ; P_SMA_BOT_5IN_DN_1.3 11.11,51.8 ; P_SMA_BOT_5IN_DN_1.3 9.99,52.93 ; P_SMA_BOT_5IN_DN_1.3 11.11,52.93 ; P_SMA_BOT_5IN_DN_1.3 9.99,51.8 ; 82.25,81.39 P_CAL_OCP_CPU_B_0_N.4 ; P_CAL_OCP_CPU_B_0_N.4 82.25,82.52 ; P_CAL_OCP_CPU_B_0_N.4 83.38,81.39 ; P_CAL_OCP_CPU_B_0_N.4 83.38,82.52 ; P_SMA_TOP_2IN_DP_2.4 71.42,66.28 ; P_SMA_TOP_2IN_DP_2.4 71.42,67.4 ; P_SMA_TOP_2IN_DP_2.4 70.29,66.28 ; P_SMA_TOP_2IN_DP_2.4 70.29,67.4 ; 157.29,51.98 P_SMA_TOP_5IN_DP_1.2 ; P_SMA_TOP_5IN_DP_1.2 158.41,50.85 ; P_SMA_TOP_5IN_DP_1.2 158.41,51.98 ; P_SMA_TOP_5IN_DP_1.2 157.29,50.85 ; 120.35,82.52 P_CAL_CPU_OCP_0_N1.4 ; P_CAL_CPU_OCP_0_N1.4 121.48,81.39 ; P_CAL_CPU_OCP_0_N1.4 121.48,82.52 ; P_CAL_CPU_OCP_0_N1.4 120.35,81.39 ; P_SMA_TOP_2IN_DN_2.3 71.42,48.63 ; P_SMA_TOP_2IN_DN_2.3 70.29,48.63 ; P_SMA_TOP_2IN_DN_2.3 71.42,47.5 ; P_SMA_TOP_2IN_DN_2.3 70.29,47.5 ; P_SMA_BOT_5IN_DP_1.2 15.41,36.37 ; P_SMA_BOT_5IN_DP_1.2 15.41,37.5 ; P_SMA_BOT_5IN_DP_1.2 14.29,37.5 ; P_SMA_BOT_5IN_DP_1.2 14.29,36.37 ; P_SMA_TOP_2IN_DN_2.4 67.12,48.63 ; P_SMA_TOP_2IN_DN_2.4 65.99,47.5 ; P_SMA_TOP_2IN_DN_2.4 67.12,47.5 ; P_SMA_TOP_2IN_DN_2.4 65.99,48.63 ; 206.2,49.58 P_SMA_BOT_2IN_DP_2.2 ; P_SMA_BOT_2IN_DP_2.2 206.2,48.45 ; P_SMA_BOT_2IN_DP_2.2 207.33,48.45 ; P_SMA_BOT_2IN_DP_2.2 207.33,49.58 ; 152.99,51.98 P_SMA_TOP_5IN_DP_1.5 ; P_SMA_TOP_5IN_DP_1.5 154.11,51.98 ; P_SMA_TOP_5IN_DP_1.5 154.11,50.85 ; P_SMA_TOP_5IN_DP_1.5 152.99,50.85 ; P_SMA_TOP_5IN_DN_2.4 267.63,67.4 ; P_SMA_TOP_5IN_DN_2.4 266.51,67.4 ; P_SMA_TOP_5IN_DN_2.4 266.51,66.28 ; P_SMA_TOP_5IN_DN_2.4 267.63,66.28 ; P_SMA_BOT_10IN_DN_1.2 243.01,19.49 ; P_SMA_BOT_10IN_DN_1.2 243.01,20.62 ; P_SMA_BOT_10IN_DN_1.2 241.89,20.62 ; P_SMA_BOT_10IN_DN_1.2 241.89,19.49 ; 34.61,37.32 P_SMA_TOP_10IN_DN_1.4 ; P_SMA_TOP_10IN_DN_1.4 35.73,37.32 ; P_SMA_TOP_10IN_DN_1.4 34.61,38.45 ; P_SMA_TOP_10IN_DN_1.4 35.73,38.45 ; 136.08,78.22 P_CAL_CPU_OCP_0_P1.4 ; P_CAL_CPU_OCP_0_P1.4 137.21,77.09 ; P_CAL_CPU_OCP_0_P1.4 137.21,78.22 ; P_CAL_CPU_OCP_0_P1.4 136.08,77.09 ; P_SMA_BOT_5IN_DP_1.3 15.41,34.15 ; P_SMA_BOT_5IN_DP_1.3 15.41,33.02 ; P_SMA_BOT_5IN_DP_1.3 14.29,34.15 ; P_SMA_BOT_5IN_DP_1.3 14.29,33.02 ; P_SMA_BOT_5IN_DN_2.2 120.33,48.45 ; P_SMA_BOT_5IN_DN_2.2 119.21,49.58 ; P_SMA_BOT_5IN_DN_2.2 120.33,49.58 ; P_SMA_BOT_5IN_DN_2.2 119.21,48.45 ; 152.99,64.05 P_SMA_TOP_5IN_DN_1.2 ; P_SMA_TOP_5IN_DN_1.2 154.11,62.93 ; P_SMA_TOP_5IN_DN_1.2 152.99,62.93 ; P_SMA_TOP_5IN_DN_1.2 154.11,64.05 ; 123.7,78.22 P_CAL_CPU_OCP_0_N1.2 ; P_CAL_CPU_OCP_0_N1.2 124.83,78.22 ; P_CAL_CPU_OCP_0_N1.2 123.7,77.09 ; P_CAL_CPU_OCP_0_N1.2 124.83,77.09 ; P_SMA_BOT_2IN_DN_1.2 211.63,36.37 ; P_SMA_BOT_2IN_DN_1.2 211.63,37.5 ; P_SMA_BOT_2IN_DN_1.2 210.5,37.5 ; P_SMA_BOT_2IN_DN_1.2 210.5,36.37 ; P_SMA_TOP_5IN_DN_1.3 154.11,66.28 ; P_SMA_TOP_5IN_DN_1.3 154.11,67.4 ; P_SMA_TOP_5IN_DN_1.3 152.99,66.28 ; P_SMA_TOP_5IN_DN_1.3 152.99,67.4 ; 262.21,35.1 P_SMA_TOP_10IN_DN_2.2 ; P_SMA_TOP_10IN_DN_2.2 263.33,33.97 ; P_SMA_TOP_10IN_DN_2.2 263.33,35.1 ; P_SMA_TOP_10IN_DN_2.2 262.21,33.97 ; 132.73,78.22 P_CAL_CPU_OCP_0_P1.5 ; P_CAL_CPU_OCP_0_P1.5 132.73,77.09 ; P_CAL_CPU_OCP_0_P1.5 133.86,77.09 ; P_CAL_CPU_OCP_0_P1.5 133.86,78.22 ; 85.6,78.22 P_CAL_OCP_CPU_B_0_N.2 ; P_CAL_OCP_CPU_B_0_N.2 86.73,78.22 ; P_CAL_OCP_CPU_B_0_N.2 86.73,77.09 ; P_CAL_OCP_CPU_B_0_N.2 85.6,77.09 ; 210.5,51.8 P_SMA_BOT_2IN_DP_2.4 ; P_SMA_BOT_2IN_DP_2.4 210.5,52.93 ; P_SMA_BOT_2IN_DP_2.4 211.63,51.8 ; P_SMA_BOT_2IN_DP_2.4 211.63,52.93 ; P_SMA_TOP_2IN_DN_2.2 71.42,51.98 ; P_SMA_TOP_2IN_DN_2.2 70.29,50.85 ; P_SMA_TOP_2IN_DN_2.2 70.29,51.98 ; P_SMA_TOP_2IN_DN_2.2 71.42,50.85 ; P_SMA_BOT_10IN_DP_1.5 243.01,8.54 ; P_SMA_BOT_10IN_DP_1.5 241.89,7.42 ; P_SMA_BOT_10IN_DP_1.5 241.89,8.54 ; P_SMA_BOT_10IN_DP_1.5 243.01,7.42 ; P_SMA_TOP_2IN_DP_1.5 35.73,64.05 ; P_SMA_TOP_2IN_DP_1.5 34.61,64.05 ; P_SMA_TOP_2IN_DP_1.5 35.73,62.93 ; P_SMA_TOP_2IN_DP_1.5 34.61,62.93 ; P_SMA_TOP_2IN_DN_1.3 35.73,48.63 ; P_SMA_TOP_2IN_DN_1.3 34.61,48.63 ; P_SMA_TOP_2IN_DN_1.3 35.73,47.5 ; P_SMA_TOP_2IN_DN_1.3 34.61,47.5 ; 246.19,33.02 P_SMA_BOT_2IN_DN_2.3 ; P_SMA_BOT_2IN_DN_2.3 247.31,33.02 ; P_SMA_BOT_2IN_DN_2.3 247.31,34.15 ; P_SMA_BOT_2IN_DN_2.3 246.19,34.15 ; P_SMA_TOP_10IN_DN_1.2 31.43,35.1 ; P_SMA_TOP_10IN_DN_1.2 30.31,35.1 ; P_SMA_TOP_10IN_DN_1.2 31.43,33.97 ; P_SMA_TOP_10IN_DN_1.2 30.31,33.97 ; 123.51,52.93 P_SMA_BOT_5IN_DN_2.4 ; P_SMA_BOT_5IN_DN_2.4 124.63,52.93 ; P_SMA_BOT_5IN_DN_2.4 123.51,51.8 ; P_SMA_BOT_5IN_DN_2.4 124.63,51.8 ; 241.89,52.93 P_SMA_BOT_2IN_DP_1.3 ; P_SMA_BOT_2IN_DP_1.3 243.01,52.93 ; P_SMA_BOT_2IN_DP_1.3 241.89,51.8 ; P_SMA_BOT_2IN_DP_1.3 243.01,51.8 ; P_SMA_TOP_10IN_DP_1.5 31.43,21.89 ; P_SMA_TOP_10IN_DP_1.5 30.31,21.89 ; P_SMA_TOP_10IN_DP_1.5 30.31,23.02 ; P_SMA_TOP_10IN_DP_1.5 31.43,23.02 ; 241.89,37.5 P_SMA_BOT_2IN_DN_2.5 ; P_SMA_BOT_2IN_DN_2.5 243.01,37.5 ; P_SMA_BOT_2IN_DN_2.5 241.89,36.37 ; P_SMA_BOT_2IN_DN_2.5 243.01,36.37 ; 266.51,33.97 P_SMA_TOP_10IN_DN_2.5 ; P_SMA_TOP_10IN_DN_2.5 266.51,35.1 ; P_SMA_TOP_10IN_DN_2.5 267.63,35.1 ; P_SMA_TOP_10IN_DN_2.5 267.63,33.97 ; P_SMA_TOP_2IN_DN_1.5 31.43,50.85 ; P_SMA_TOP_2IN_DN_1.5 31.43,51.98 ; P_SMA_TOP_2IN_DN_1.5 30.31,50.85 ; P_SMA_TOP_2IN_DN_1.5 30.31,51.98 ; P_CAL_OCP_CPU_B_0_P.5 95.76,78.22 ; P_CAL_OCP_CPU_B_0_P.5 95.76,77.09 ; P_CAL_OCP_CPU_B_0_P.5 94.63,77.09 ; P_CAL_OCP_CPU_B_0_P.5 94.63,78.22 ; P_SMA_TOP_5IN_DN_2.3 263.33,67.4 ; P_SMA_TOP_5IN_DN_2.3 262.21,67.4 ; P_SMA_TOP_5IN_DN_2.3 263.33,66.28 ; P_SMA_TOP_5IN_DN_2.3 262.21,66.28 ; 34.61,51.98 P_SMA_TOP_2IN_DN_1.2 ; P_SMA_TOP_2IN_DN_1.2 35.73,50.85 ; P_SMA_TOP_2IN_DN_1.2 34.61,50.85 ; P_SMA_TOP_2IN_DN_1.2 35.73,51.98 ; P_SMA_BOT_2IN_DP_2.3 207.33,51.8 ; P_SMA_BOT_2IN_DP_2.3 206.2,51.8 ; P_SMA_BOT_2IN_DP_2.3 206.2,52.93 ; P_SMA_BOT_2IN_DP_2.3 207.33,52.93 ; 30.31,19.67 P_SMA_TOP_10IN_DP_1.4 ; P_SMA_TOP_10IN_DP_1.4 30.31,18.54 ; P_SMA_TOP_10IN_DP_1.4 31.43,18.54 ; P_SMA_TOP_10IN_DP_1.4 31.43,19.67 ; 9.99,48.45 P_SMA_BOT_5IN_DN_1.2 ; P_SMA_BOT_5IN_DN_1.2 9.99,49.58 ; P_SMA_BOT_5IN_DN_1.2 11.11,49.58 ; P_SMA_BOT_5IN_DN_1.2 11.11,48.45 ; P_SMA_TOP_2IN_DP_2.3 67.12,66.28 ; P_SMA_TOP_2IN_DP_2.3 67.12,67.4 ; P_SMA_TOP_2IN_DP_2.3 65.99,66.28 ; P_SMA_TOP_2IN_DP_2.3 65.99,67.4 ; P_SMA_BOT_2IN_DN_1.4 207.33,33.02 ; P_SMA_BOT_2IN_DN_1.4 206.2,33.02 ; P_SMA_BOT_2IN_DN_1.4 206.2,34.15 ; P_SMA_BOT_2IN_DN_1.4 207.33,34.15 ; 34.61,66.28 P_SMA_TOP_2IN_DP_1.4 ; P_SMA_TOP_2IN_DP_1.4 34.61,67.4 ; P_SMA_TOP_2IN_DP_1.4 35.73,67.4 ; P_SMA_TOP_2IN_DP_1.4 35.73,66.28 ; P_SMA_TOP_5IN_DP_2.3 267.63,48.63 ; P_SMA_TOP_5IN_DP_2.3 267.63,47.5 ; P_SMA_TOP_5IN_DP_2.3 266.51,47.5 ; P_SMA_TOP_5IN_DP_2.3 266.51,48.63 ; 241.89,49.58 P_SMA_BOT_2IN_DP_1.2 ; P_SMA_BOT_2IN_DP_1.2 243.01,49.58 ; P_SMA_BOT_2IN_DP_1.2 243.01,48.45 ; P_SMA_BOT_2IN_DP_1.2 241.89,48.45 ; 246.19,52.93 P_SMA_BOT_2IN_DP_1.4 ; P_SMA_BOT_2IN_DP_1.4 247.31,51.8 ; P_SMA_BOT_2IN_DP_1.4 247.31,52.93 ; P_SMA_BOT_2IN_DP_1.4 246.19,51.8 ; P_CAL_OCP_CPU_B_0_N.3 83.38,78.22 ; P_CAL_OCP_CPU_B_0_N.3 82.25,78.22 ; P_CAL_OCP_CPU_B_0_N.3 83.38,77.09 ; P_CAL_OCP_CPU_B_0_N.3 82.25,77.09 ; P_SMA_BOT_2IN_DP_1.5 247.31,49.58 ; P_SMA_BOT_2IN_DP_1.5 246.19,49.58 ; P_SMA_BOT_2IN_DP_1.5 246.19,48.45 ; P_SMA_BOT_2IN_DP_1.5 247.31,48.45 ; P_SMA_BOT_10IN_DN_1.3 243.01,23.97 ; P_SMA_BOT_10IN_DN_1.3 243.01,22.84 ; P_SMA_BOT_10IN_DN_1.3 241.89,23.97 ; P_SMA_BOT_10IN_DN_1.3 241.89,22.84 ; P_SMA_BOT_10IN_DP_2.3 15.41,5.19 ; P_SMA_BOT_10IN_DP_2.3 15.41,4.07 ; P_SMA_BOT_10IN_DP_2.3 14.29,5.19 ; P_SMA_BOT_10IN_DP_2.3 14.29,4.07 ; P_SMA_TOP_5IN_DP_2.2 267.63,51.98 ; P_SMA_TOP_5IN_DP_2.2 267.63,50.85 ; P_SMA_TOP_5IN_DP_2.2 266.51,50.85 ; P_SMA_TOP_5IN_DP_2.2 266.51,51.98 ; P_SMA_BOT_10IN_DN_1.4 247.31,22.84 ; P_SMA_BOT_10IN_DN_1.4 246.19,22.84 ; P_SMA_BOT_10IN_DN_1.4 247.31,23.97 ; P_SMA_BOT_10IN_DN_1.4 246.19,23.97 ; 119.21,36.37 P_SMA_BOT_5IN_DP_2.5 ; P_SMA_BOT_5IN_DP_2.5 120.33,36.37 ; P_SMA_BOT_5IN_DP_2.5 120.33,37.5 ; P_SMA_BOT_5IN_DP_2.5 119.21,37.5 ; P_SMA_BOT_10IN_DP_2.4 11.11,4.07 ; P_SMA_BOT_10IN_DP_2.4 9.99,5.19 ; P_SMA_BOT_10IN_DP_2.4 11.11,5.19 ; P_SMA_BOT_10IN_DP_2.4 9.99,4.07 ; 119.21,34.15 P_SMA_BOT_5IN_DP_2.4 ; P_SMA_BOT_5IN_DP_2.4 120.33,33.02 ; P_SMA_BOT_5IN_DP_2.4 119.21,33.02 ; P_SMA_BOT_5IN_DP_2.4 120.33,34.15 ; 246.19,37.5 P_SMA_BOT_2IN_DN_2.2 ; P_SMA_BOT_2IN_DN_2.2 247.31,36.37 ; P_SMA_BOT_2IN_DN_2.2 247.31,37.5 ; P_SMA_BOT_2IN_DN_2.2 246.19,36.37 ; P_SMA_TOP_2IN_DP_2.2 67.12,64.05 ; P_SMA_TOP_2IN_DP_2.2 67.12,62.93 ; P_SMA_TOP_2IN_DP_2.2 65.99,64.05 ; P_SMA_TOP_2IN_DP_2.2 65.99,62.93 ; 123.51,34.15 P_SMA_BOT_5IN_DP_2.3 ; P_SMA_BOT_5IN_DP_2.3 124.63,34.15 ; P_SMA_BOT_5IN_DP_2.3 124.63,33.02 ; P_SMA_BOT_5IN_DP_2.3 123.51,33.02 ; P_SMA_TOP_5IN_DP_1.3 158.41,47.5 ; P_SMA_TOP_5IN_DP_1.3 158.41,48.63 ; P_SMA_TOP_5IN_DP_1.3 157.29,48.63 ; P_SMA_TOP_5IN_DP_1.3 157.29,47.5 ; 97.98,78.22 P_CAL_OCP_CPU_B_0_P.4 ; P_CAL_OCP_CPU_B_0_P.4 99.11,78.22 ; P_CAL_OCP_CPU_B_0_P.4 97.98,77.09 ; P_CAL_OCP_CPU_B_0_P.4 99.11,77.09 ; P_SMA_BOT_10IN_DP_2.2 15.41,8.54 ; P_SMA_BOT_10IN_DP_2.2 14.29,8.54 ; P_SMA_BOT_10IN_DP_2.2 14.29,7.42 ; P_SMA_BOT_10IN_DP_2.2 15.41,7.42 ; P_SMA_BOT_10IN_DN_2.2 11.11,19.49 ; P_SMA_BOT_10IN_DN_2.2 11.11,20.62 ; P_SMA_BOT_10IN_DN_2.2 9.99,19.49 ; P_SMA_BOT_10IN_DN_2.2 9.99,20.62 ; P_SMA_BOT_10IN_DN_2.3 11.11,23.97 ; P_SMA_BOT_10IN_DN_2.3 9.99,23.97 ; P_SMA_BOT_10IN_DN_2.3 11.11,22.84 ; P_SMA_BOT_10IN_DN_2.3 9.99,22.84 ; P_SMA_TOP_5IN_DN_1.5 158.41,64.05 ; P_SMA_TOP_5IN_DN_1.5 157.29,62.93 ; P_SMA_TOP_5IN_DN_1.5 157.29,64.05 ; P_SMA_TOP_5IN_DN_1.5 158.41,62.93 ; 34.61,35.1 P_SMA_TOP_10IN_DN_1.5 ; P_SMA_TOP_10IN_DN_1.5 34.61,33.97 ; P_SMA_TOP_10IN_DN_1.5 35.73,35.1 ; P_SMA_TOP_10IN_DN_1.5 35.73,33.97 ; 123.51,49.58 P_SMA_BOT_5IN_DN_2.5 ; P_SMA_BOT_5IN_DN_2.5 124.63,48.45 ; P_SMA_BOT_5IN_DN_2.5 123.51,48.45 ; P_SMA_BOT_5IN_DN_2.5 124.63,49.58 ; P_SMA_TOP_2IN_DP_2.5 71.42,62.93 ; P_SMA_TOP_2IN_DP_2.5 70.29,62.93 ; P_SMA_TOP_2IN_DP_2.5 70.29,64.05 ; P_SMA_TOP_2IN_DP_2.5 71.42,64.05 ; 262.21,38.45 P_SMA_TOP_10IN_DN_2.3 ; P_SMA_TOP_10IN_DN_2.3 262.21,37.32 ; P_SMA_TOP_10IN_DN_2.3 263.33,37.32 ; P_SMA_TOP_10IN_DN_2.3 263.33,38.45 ; 246.19,7.42 P_SMA_BOT_10IN_DP_1.2 ; P_SMA_BOT_10IN_DP_1.2 247.31,8.54 ; P_SMA_BOT_10IN_DP_1.2 247.31,7.42 ; P_SMA_BOT_10IN_DP_1.2 246.19,8.54 ; 132.73,82.52 P_CAL_CPU_OCP_0_P1.2 ; P_CAL_CPU_OCP_0_P1.2 133.86,81.39 ; P_CAL_CPU_OCP_0_P1.2 132.73,81.39 ; P_CAL_CPU_OCP_0_P1.2 133.86,82.52 ; 262.21,51.98 P_SMA_TOP_5IN_DP_2.5 ; P_SMA_TOP_5IN_DP_2.5 262.21,50.85 ; P_SMA_TOP_5IN_DP_2.5 263.33,51.98 ; P_SMA_TOP_5IN_DP_2.5 263.33,50.85 ; P_SMA_TOP_10IN_DP_2.5 263.33,21.89 ; P_SMA_TOP_10IN_DP_2.5 262.21,23.02 ; P_SMA_TOP_10IN_DP_2.5 263.33,23.02 ; P_SMA_TOP_10IN_DP_2.5 262.21,21.89 ; P_SMA_TOP_5IN_DP_1.4 154.11,48.63 ; P_SMA_TOP_5IN_DP_1.4 152.99,48.63 ; P_SMA_TOP_5IN_DP_1.4 154.11,47.5 ; P_SMA_TOP_5IN_DP_1.4 152.99,47.5
  VCC w0.254: P_SMA_BOT_10IN_DN_1.2 243.01,19.49 ; P_SMA_BOT_10IN_DN_1.2 243.01,20.62 ; P_SMA_BOT_10IN_DN_1.2 241.89,20.62 ; P_SMA_BOT_10IN_DN_1.2 241.89,19.49 ; 119.21,52.93 P_SMA_BOT_5IN_DN_2.3 ; P_SMA_BOT_5IN_DN_2.3 120.33,52.93 ; P_SMA_BOT_5IN_DN_2.3 119.21,51.8 ; P_SMA_BOT_5IN_DN_2.3 120.33,51.8 ; P_SMA_TOP_5IN_DN_2.3 263.33,67.4 ; P_SMA_TOP_5IN_DN_2.3 263.33,66.28 ; P_SMA_TOP_5IN_DN_2.3 262.21,66.28 ; P_SMA_TOP_5IN_DN_2.3 262.21,67.4 ; P_SMA_TOP_5IN_DP_2.5 263.33,51.98 ; P_SMA_TOP_5IN_DP_2.5 263.33,50.85 ; P_SMA_TOP_5IN_DP_2.5 262.21,50.85 ; P_SMA_TOP_5IN_DP_2.5 262.21,51.98 ; P_SMA_TOP_2IN_DN_1.3 35.73,47.5 ; P_SMA_TOP_2IN_DN_1.3 35.73,48.63 ; P_SMA_TOP_2IN_DN_1.3 34.61,47.5 ; P_SMA_TOP_2IN_DN_1.3 34.61,48.63 ; P_SMA_TOP_5IN_DN_2.2 263.33,64.05 ; P_SMA_TOP_5IN_DN_2.2 262.21,64.05 ; P_SMA_TOP_5IN_DN_2.2 262.21,62.93 ; P_SMA_TOP_5IN_DN_2.2 263.33,62.93 ; P_SMA_TOP_10IN_DN_1.2 31.43,35.1 ; P_SMA_TOP_10IN_DN_1.2 30.31,33.97 ; P_SMA_TOP_10IN_DN_1.2 31.43,33.97 ; P_SMA_TOP_10IN_DN_1.2 30.31,35.1 ; P_SMA_TOP_2IN_DN_2.4 67.12,47.5 ; P_SMA_TOP_2IN_DN_2.4 67.12,48.63 ; P_SMA_TOP_2IN_DN_2.4 65.99,48.63 ; P_SMA_TOP_2IN_DN_2.4 65.99,47.5 ; 9.99,22.84 P_SMA_BOT_10IN_DN_2.3 ; P_SMA_BOT_10IN_DN_2.3 11.11,23.97 ; P_SMA_BOT_10IN_DN_2.3 9.99,23.97 ; P_SMA_BOT_10IN_DN_2.3 11.11,22.84 ; 14.29,37.5 P_SMA_BOT_5IN_DP_1.2 ; P_SMA_BOT_5IN_DP_1.2 15.41,36.37 ; P_SMA_BOT_5IN_DP_1.2 14.29,36.37 ; P_SMA_BOT_5IN_DP_1.2 15.41,37.5 ; 14.29,7.42 P_SMA_BOT_10IN_DP_2.2 ; P_SMA_BOT_10IN_DP_2.2 14.29,8.54 ; P_SMA_BOT_10IN_DP_2.2 15.41,8.54 ; P_SMA_BOT_10IN_DP_2.2 15.41,7.42 ; 136.08,81.39 P_CAL_CPU_OCP_0_P1.3 ; P_CAL_CPU_OCP_0_P1.3 137.21,81.39 ; P_CAL_CPU_OCP_0_P1.3 136.08,82.52 ; P_CAL_CPU_OCP_0_P1.3 137.21,82.52 ; 246.19,19.49 P_SMA_BOT_10IN_DN_1.5 ; P_SMA_BOT_10IN_DN_1.5 247.31,20.62 ; P_SMA_BOT_10IN_DN_1.5 246.19,20.62 ; P_SMA_BOT_10IN_DN_1.5 247.31,19.49 ; P_SMA_TOP_10IN_DN_1.3 31.43,37.32 ; P_SMA_TOP_10IN_DN_1.3 31.43,38.45 ; P_SMA_TOP_10IN_DN_1.3 30.31,37.32 ; P_SMA_TOP_10IN_DN_1.3 30.31,38.45 ; 70.29,51.98 P_SMA_TOP_2IN_DN_2.2 ; P_SMA_TOP_2IN_DN_2.2 70.29,50.85 ; P_SMA_TOP_2IN_DN_2.2 71.42,50.85 ; P_SMA_TOP_2IN_DN_2.2 71.42,51.98 ; P_SMA_BOT_10IN_DP_1.5 243.01,7.42 ; P_SMA_BOT_10IN_DP_1.5 241.89,8.54 ; P_SMA_BOT_10IN_DP_1.5 243.01,8.54 ; P_SMA_BOT_10IN_DP_1.5 241.89,7.42 ; 262.21,18.54 P_SMA_TOP_10IN_DP_2.4 ; P_SMA_TOP_10IN_DP_2.4 263.33,19.67 ; P_SMA_TOP_10IN_DP_2.4 263.33,18.54 ; P_SMA_TOP_10IN_DP_2.4 262.21,19.67 ; 34.61,35.1 P_SMA_TOP_10IN_DN_1.5 ; P_SMA_TOP_10IN_DN_1.5 34.61,33.97 ; P_SMA_TOP_10IN_DN_1.5 35.73,33.97 ; P_SMA_TOP_10IN_DN_1.5 35.73,35.1 ; P_CAL_OCP_CPU_B_0_N.2 86.73,77.09 ; P_CAL_OCP_CPU_B_0_N.2 85.6,77.09 ; P_CAL_OCP_CPU_B_0_N.2 86.73,78.22 ; P_CAL_OCP_CPU_B_0_N.2 85.6,78.22 ; P_SMA_TOP_5IN_DP_1.4 154.11,48.63 ; P_SMA_TOP_5IN_DP_1.4 152.99,47.5 ; P_SMA_TOP_5IN_DP_1.4 152.99,48.63 ; P_SMA_TOP_5IN_DP_1.4 154.11,47.5 ; P_SMA_BOT_5IN_DP_2.5 120.33,37.5 ; P_SMA_BOT_5IN_DP_2.5 119.21,37.5 ; P_SMA_BOT_5IN_DP_2.5 119.21,36.37 ; P_SMA_BOT_5IN_DP_2.5 120.33,36.37 ; P_SMA_BOT_5IN_DN_2.2 120.33,48.45 ; P_SMA_BOT_5IN_DN_2.2 120.33,49.58 ; P_SMA_BOT_5IN_DN_2.2 119.21,49.58 ; P_SMA_BOT_5IN_DN_2.2 119.21,48.45 ; P_SMA_TOP_5IN_DP_2.4 263.33,48.63 ; P_SMA_TOP_5IN_DP_2.4 262.21,48.63 ; P_SMA_TOP_5IN_DP_2.4 263.33,47.5 ; P_SMA_TOP_5IN_DP_2.4 262.21,47.5 ; 152.99,66.28 P_SMA_TOP_5IN_DN_1.3 ; P_SMA_TOP_5IN_DN_1.3 152.99,67.4 ; P_SMA_TOP_5IN_DN_1.3 154.11,66.28 ; P_SMA_TOP_5IN_DN_1.3 154.11,67.4 ; 157.29,47.5 P_SMA_TOP_5IN_DP_1.3 ; P_SMA_TOP_5IN_DP_1.3 158.41,47.5 ; P_SMA_TOP_5IN_DP_1.3 158.41,48.63 ; P_SMA_TOP_5IN_DP_1.3 157.29,48.63 ; P_SMA_BOT_10IN_DP_2.4 11.11,4.07 ; P_SMA_BOT_10IN_DP_2.4 11.11,5.19 ; P_SMA_BOT_10IN_DP_2.4 9.99,5.19 ; P_SMA_BOT_10IN_DP_2.4 9.99,4.07 ; P_SMA_TOP_5IN_DN_1.5 158.41,62.93 ; P_SMA_TOP_5IN_DN_1.5 158.41,64.05 ; P_SMA_TOP_5IN_DN_1.5 157.29,62.93 ; P_SMA_TOP_5IN_DN_1.5 157.29,64.05 ; P_SMA_TOP_10IN_DP_1.5 31.43,23.02 ; P_SMA_TOP_10IN_DP_1.5 31.43,21.89 ; P_SMA_TOP_10IN_DP_1.5 30.31,23.02 ; P_SMA_TOP_10IN_DP_1.5 30.31,21.89 ; P_SMA_TOP_10IN_DN_2.3 263.33,38.45 ; P_SMA_TOP_10IN_DN_2.3 262.21,38.45 ; P_SMA_TOP_10IN_DN_2.3 262.21,37.32 ; P_SMA_TOP_10IN_DN_2.3 263.33,37.32 ; P_SMA_BOT_5IN_DP_1.4 11.11,34.15 ; P_SMA_BOT_5IN_DP_1.4 9.99,33.02 ; P_SMA_BOT_5IN_DP_1.4 11.11,33.02 ; P_SMA_BOT_5IN_DP_1.4 9.99,34.15 ; 206.2,37.5 P_SMA_BOT_2IN_DN_1.5 ; P_SMA_BOT_2IN_DN_1.5 207.33,36.37 ; P_SMA_BOT_2IN_DN_1.5 206.2,36.37 ; P_SMA_BOT_2IN_DN_1.5 207.33,37.5 ; 14.29,33.02 P_SMA_BOT_5IN_DP_1.3 ; P_SMA_BOT_5IN_DP_1.3 15.41,33.02 ; P_SMA_BOT_5IN_DP_1.3 15.41,34.15 ; P_SMA_BOT_5IN_DP_1.3 14.29,34.15 ; 97.98,81.39 P_CAL_OCP_CPU_B_0_P.3 ; P_CAL_OCP_CPU_B_0_P.3 99.11,82.52 ; P_CAL_OCP_CPU_B_0_P.3 97.98,82.52 ; P_CAL_OCP_CPU_B_0_P.3 99.11,81.39 ; 30.31,18.54 P_SMA_TOP_10IN_DP_1.4 ; P_SMA_TOP_10IN_DP_1.4 31.43,18.54 ; P_SMA_TOP_10IN_DP_1.4 31.43,19.67 ; P_SMA_TOP_10IN_DP_1.4 30.31,19.67 ; 157.29,51.98 P_SMA_TOP_5IN_DP_1.2 ; P_SMA_TOP_5IN_DP_1.2 158.41,51.98 ; P_SMA_TOP_5IN_DP_1.2 157.29,50.85 ; P_SMA_TOP_5IN_DP_1.2 158.41,50.85 ; P_CAL_CPU_OCP_0_N1.5 124.83,82.52 ; P_CAL_CPU_OCP_0_N1.5 124.83,81.39 ; P_CAL_CPU_OCP_0_N1.5 123.7,81.39 ; P_CAL_CPU_OCP_0_N1.5 123.7,82.52 ; 9.99,52.93 P_SMA_BOT_5IN_DN_1.3 ; P_SMA_BOT_5IN_DN_1.3 11.11,52.93 ; P_SMA_BOT_5IN_DN_1.3 11.11,51.8 ; P_SMA_BOT_5IN_DN_1.3 9.99,51.8 ; 206.2,51.8 P_SMA_BOT_2IN_DP_2.3 ; P_SMA_BOT_2IN_DP_2.3 206.2,52.93 ; P_SMA_BOT_2IN_DP_2.3 207.33,51.8 ; P_SMA_BOT_2IN_DP_2.3 207.33,52.93 ; 241.89,4.07 P_SMA_BOT_10IN_DP_1.4 ; P_SMA_BOT_10IN_DP_1.4 241.89,5.19 ; P_SMA_BOT_10IN_DP_1.4 243.01,5.19 ; P_SMA_BOT_10IN_DP_1.4 243.01,4.07 ; P_SMA_BOT_2IN_DN_2.2 247.31,36.37 ; P_SMA_BOT_2IN_DN_2.2 246.19,36.37 ; P_SMA_BOT_2IN_DN_2.2 246.19,37.5 ; P_SMA_BOT_2IN_DN_2.2 247.31,37.5 ; 14.29,48.45 P_SMA_BOT_5IN_DN_1.5 ; P_SMA_BOT_5IN_DN_1.5 15.41,48.45 ; P_SMA_BOT_5IN_DN_1.5 15.41,49.58 ; P_SMA_BOT_5IN_DN_1.5 14.29,49.58 ; P_SMA_TOP_5IN_DP_1.5 154.11,51.98 ; P_SMA_TOP_5IN_DP_1.5 152.99,50.85 ; P_SMA_TOP_5IN_DP_1.5 154.11,50.85 ; P_SMA_TOP_5IN_DP_1.5 152.99,51.98 ; P_SMA_BOT_2IN_DP_1.3 243.01,51.8 ; P_SMA_BOT_2IN_DP_1.3 241.89,52.93 ; P_SMA_BOT_2IN_DP_1.3 241.89,51.8 ; P_SMA_BOT_2IN_DP_1.3 243.01,52.93 ; P_SMA_TOP_2IN_DN_2.5 67.12,50.85 ; P_SMA_TOP_2IN_DN_2.5 67.12,51.98 ; P_SMA_TOP_2IN_DN_2.5 65.99,50.85 ; P_SMA_TOP_2IN_DN_2.5 65.99,51.98 ; P_SMA_TOP_2IN_DP_1.5 35.73,64.05 ; P_SMA_TOP_2IN_DP_1.5 34.61,64.05 ; P_SMA_TOP_2IN_DP_1.5 35.73,62.93 ; P_SMA_TOP_2IN_DP_1.5 34.61,62.93 ; P_SMA_BOT_10IN_DN_2.2 11.11,20.62 ; P_SMA_BOT_10IN_DN_2.2 9.99,20.62 ; P_SMA_BOT_10IN_DN_2.2 11.11,19.49 ; P_SMA_BOT_10IN_DN_2.2 9.99,19.49 ; P_SMA_BOT_10IN_DP_2.5 11.11,7.42 ; P_SMA_BOT_10IN_DP_2.5 11.11,8.54 ; P_SMA_BOT_10IN_DP_2.5 9.99,8.54 ; P_SMA_BOT_10IN_DP_2.5 9.99,7.42 ; 210.5,52.93 P_SMA_BOT_2IN_DP_2.4 ; P_SMA_BOT_2IN_DP_2.4 210.5,51.8 ; P_SMA_BOT_2IN_DP_2.4 211.63,52.93 ; P_SMA_BOT_2IN_DP_2.4 211.63,51.8 ; P_CAL_OCP_CPU_B_0_P.2 95.76,81.39 ; P_CAL_OCP_CPU_B_0_P.2 95.76,82.52 ; P_CAL_OCP_CPU_B_0_P.2 94.63,82.52 ; P_CAL_OCP_CPU_B_0_P.2 94.63,81.39 ; P_SMA_TOP_10IN_DN_2.4 267.63,38.45 ; P_SMA_TOP_10IN_DN_2.4 266.51,38.45 ; P_SMA_TOP_10IN_DN_2.4 267.63,37.32 ; P_SMA_TOP_10IN_DN_2.4 266.51,37.32 ; P_SMA_BOT_10IN_DP_1.2 247.31,8.54 ; P_SMA_BOT_10IN_DP_1.2 246.19,7.42 ; P_SMA_BOT_10IN_DP_1.2 246.19,8.54 ; P_SMA_BOT_10IN_DP_1.2 247.31,7.42 ; P_SMA_TOP_2IN_DN_1.2 35.73,51.98 ; P_SMA_TOP_2IN_DN_1.2 34.61,51.98 ; P_SMA_TOP_2IN_DN_1.2 34.61,50.85 ; P_SMA_TOP_2IN_DN_1.2 35.73,50.85 ; P_SMA_BOT_5IN_DN_2.5 124.63,49.58 ; P_SMA_BOT_5IN_DN_2.5 123.51,49.58 ; P_SMA_BOT_5IN_DN_2.5 123.51,48.45 ; P_SMA_BOT_5IN_DN_2.5 124.63,48.45 ; 210.5,34.15 P_SMA_BOT_2IN_DN_1.3 ; P_SMA_BOT_2IN_DN_1.3 211.63,33.02 ; P_SMA_BOT_2IN_DN_1.3 211.63,34.15 ; P_SMA_BOT_2IN_DN_1.3 210.5,33.02 ; 30.31,64.05 P_SMA_TOP_2IN_DP_1.2 ; P_SMA_TOP_2IN_DP_1.2 31.43,64.05 ; P_SMA_TOP_2IN_DP_1.2 30.31,62.93 ; P_SMA_TOP_2IN_DP_1.2 31.43,62.93 ; P_SMA_BOT_10IN_DN_1.3 243.01,23.97 ; P_SMA_BOT_10IN_DN_1.3 241.89,23.97 ; P_SMA_BOT_10IN_DN_1.3 241.89,22.84 ; P_SMA_BOT_10IN_DN_1.3 243.01,22.84 ; 266.51,64.05 P_SMA_TOP_5IN_DN_2.5 ; P_SMA_TOP_5IN_DN_2.5 267.63,62.93 ; P_SMA_TOP_5IN_DN_2.5 266.51,62.93 ; P_SMA_TOP_5IN_DN_2.5 267.63,64.05 ; P_SMA_BOT_10IN_DN_2.4 15.41,22.84 ; P_SMA_BOT_10IN_DN_2.4 14.29,23.97 ; P_SMA_BOT_10IN_DN_2.4 15.41,23.97 ; P_SMA_BOT_10IN_DN_2.4 14.29,22.84 ; 157.29,66.28 P_SMA_TOP_5IN_DN_1.4 ; P_SMA_TOP_5IN_DN_1.4 157.29,67.4 ; P_SMA_TOP_5IN_DN_1.4 158.41,67.4 ; P_SMA_TOP_5IN_DN_1.4 158.41,66.28 ; P_SMA_TOP_10IN_DN_2.2 263.33,33.97 ; P_SMA_TOP_10IN_DN_2.2 263.33,35.1 ; P_SMA_TOP_10IN_DN_2.2 262.21,33.97 ; P_SMA_TOP_10IN_DN_2.2 262.21,35.1 ; P_SMA_TOP_10IN_DP_1.3 35.73,19.67 ; P_SMA_TOP_10IN_DP_1.3 34.61,18.54 ; P_SMA_TOP_10IN_DP_1.3 35.73,18.54 ; P_SMA_TOP_10IN_DP_1.3 34.61,19.67 ; 266.51,51.98 P_SMA_TOP_5IN_DP_2.2 ; P_SMA_TOP_5IN_DP_2.2 266.51,50.85 ; P_SMA_TOP_5IN_DP_2.2 267.63,50.85 ; P_SMA_TOP_5IN_DP_2.2 267.63,51.98 ; 152.99,62.93 P_SMA_TOP_5IN_DN_1.2 ; P_SMA_TOP_5IN_DN_1.2 154.11,62.93 ; P_SMA_TOP_5IN_DN_1.2 152.99,64.05 ; P_SMA_TOP_5IN_DN_1.2 154.11,64.05 ; P_SMA_BOT_5IN_DN_2.4 124.63,52.93 ; P_SMA_BOT_5IN_DN_2.4 123.51,51.8 ; P_SMA_BOT_5IN_DN_2.4 123.51,52.93 ; P_SMA_BOT_5IN_DN_2.4 124.63,51.8 ; P_SMA_BOT_2IN_DP_1.4 247.31,52.93 ; P_SMA_BOT_2IN_DP_1.4 246.19,51.8 ; P_SMA_BOT_2IN_DP_1.4 247.31,51.8 ; P_SMA_BOT_2IN_DP_1.4 246.19,52.93 ; 14.29,5.19 P_SMA_BOT_10IN_DP_2.3 ; P_SMA_BOT_10IN_DP_2.3 14.29,4.07 ; P_SMA_BOT_10IN_DP_2.3 15.41,4.07 ; P_SMA_BOT_10IN_DP_2.3 15.41,5.19 ; P_CAL_CPU_OCP_0_P1.4 137.21,77.09 ; P_CAL_CPU_OCP_0_P1.4 136.08,78.22 ; P_CAL_CPU_OCP_0_P1.4 137.21,78.22 ; P_CAL_CPU_OCP_0_P1.4 136.08,77.09 ; P_SMA_BOT_2IN_DN_2.5 243.01,36.37 ; P_SMA_BOT_2IN_DN_2.5 241.89,36.37 ; P_SMA_BOT_2IN_DN_2.5 241.89,37.5 ; P_SMA_BOT_2IN_DN_2.5 243.01,37.5 ; 9.99,49.58 P_SMA_BOT_5IN_DN_1.2 ; P_SMA_BOT_5IN_DN_1.2 11.11,48.45 ; P_SMA_BOT_5IN_DN_1.2 11.11,49.58 ; P_SMA_BOT_5IN_DN_1.2 9.99,48.45 ; 120.35,77.09 P_CAL_CPU_OCP_0_N1.3 ; P_CAL_CPU_OCP_0_N1.3 121.48,78.22 ; P_CAL_CPU_OCP_0_N1.3 120.35,78.22 ; P_CAL_CPU_OCP_0_N1.3 121.48,77.09 ; 241.89,48.45 P_SMA_BOT_2IN_DP_1.2 ; P_SMA_BOT_2IN_DP_1.2 243.01,49.58 ; P_SMA_BOT_2IN_DP_1.2 243.01,48.45 ; P_SMA_BOT_2IN_DP_1.2 241.89,49.58 ; P_SMA_TOP_2IN_DP_2.5 71.42,62.93 ; P_SMA_TOP_2IN_DP_2.5 71.42,64.05 ; P_SMA_TOP_2IN_DP_2.5 70.29,62.93 ; P_SMA_TOP_2IN_DP_2.5 70.29,64.05 ; 65.99,64.05 P_SMA_TOP_2IN_DP_2.2 ; P_SMA_TOP_2IN_DP_2.2 65.99,62.93 ; P_SMA_TOP_2IN_DP_2.2 67.12,64.05 ; P_SMA_TOP_2IN_DP_2.2 67.12,62.93 ; 210.5,49.58 P_SMA_BOT_2IN_DP_2.5 ; P_SMA_BOT_2IN_DP_2.5 211.63,48.45 ; P_SMA_BOT_2IN_DP_2.5 210.5,48.45 ; P_SMA_BOT_2IN_DP_2.5 211.63,49.58 ; P_SMA_BOT_5IN_DP_2.2 124.63,37.5 ; P_SMA_BOT_5IN_DP_2.2 123.51,36.37 ; P_SMA_BOT_5IN_DP_2.2 123.51,37.5 ; P_SMA_BOT_5IN_DP_2.2 124.63,36.37 ; 123.7,77.09 P_CAL_CPU_OCP_0_N1.2 ; P_CAL_CPU_OCP_0_N1.2 124.83,78.22 ; P_CAL_CPU_OCP_0_N1.2 123.7,78.22 ; P_CAL_CPU_OCP_0_N1.2 124.83,77.09 ; P_SMA_TOP_10IN_DP_1.2 35.73,23.02 ; P_SMA_TOP_10IN_DP_1.2 34.61,21.89 ; P_SMA_TOP_10IN_DP_1.2 34.61,23.02 ; P_SMA_TOP_10IN_DP_1.2 35.73,21.89 ; 85.6,81.39 P_CAL_OCP_CPU_B_0_N.5 ; P_CAL_OCP_CPU_B_0_N.5 86.73,81.39 ; P_CAL_OCP_CPU_B_0_N.5 86.73,82.52 ; P_CAL_OCP_CPU_B_0_N.5 85.6,82.52 ; 9.99,36.37 P_SMA_BOT_5IN_DP_1.5 ; P_SMA_BOT_5IN_DP_1.5 9.99,37.5 ; P_SMA_BOT_5IN_DP_1.5 11.11,36.37 ; P_SMA_BOT_5IN_DP_1.5 11.11,37.5 ; 246.19,33.02 P_SMA_BOT_2IN_DN_2.3 ; P_SMA_BOT_2IN_DN_2.3 246.19,34.15 ; P_SMA_BOT_2IN_DN_2.3 247.31,33.02 ; P_SMA_BOT_2IN_DN_2.3 247.31,34.15 ; 119.21,34.15 P_SMA_BOT_5IN_DP_2.4 ; P_SMA_BOT_5IN_DP_2.4 120.33,34.15 ; P_SMA_BOT_5IN_DP_2.4 120.33,33.02 ; P_SMA_BOT_5IN_DP_2.4 119.21,33.02 ; P_SMA_TOP_2IN_DP_2.3 67.12,67.4 ; P_SMA_TOP_2IN_DP_2.3 67.12,66.28 ; P_SMA_TOP_2IN_DP_2.3 65.99,67.4 ; P_SMA_TOP_2IN_DP_2.3 65.99,66.28 ; 14.29,52.93 P_SMA_BOT_5IN_DN_1.4 ; P_SMA_BOT_5IN_DN_1.4 15.41,52.93 ; P_SMA_BOT_5IN_DN_1.4 15.41,51.8 ; P_SMA_BOT_5IN_DN_1.4 14.29,51.8 ; P_SMA_BOT_2IN_DN_2.4 243.01,34.15 ; P_SMA_BOT_2IN_DN_2.4 241.89,34.15 ; P_SMA_BOT_2IN_DN_2.4 241.89,33.02 ; P_SMA_BOT_2IN_DN_2.4 243.01,33.02 ; P_CAL_OCP_CPU_B_0_N.3 83.38,78.22 ; P_CAL_OCP_CPU_B_0_N.3 82.25,78.22 ; P_CAL_OCP_CPU_B_0_N.3 82.25,77.09 ; P_CAL_OCP_CPU_B_0_N.3 83.38,77.09 ; P_SMA_BOT_10IN_DN_2.5 15.41,20.62 ; P_SMA_BOT_10IN_DN_2.5 14.29,19.49 ; P_SMA_BOT_10IN_DN_2.5 15.41,19.49 ; P_SMA_BOT_10IN_DN_2.5 14.29,20.62 ; 206.2,34.15 P_SMA_BOT_2IN_DN_1.4 ; P_SMA_BOT_2IN_DN_1.4 206.2,33.02 ; P_SMA_BOT_2IN_DN_1.4 207.33,33.02 ; P_SMA_BOT_2IN_DN_1.4 207.33,34.15 ; 94.63,77.09 P_CAL_OCP_CPU_B_0_P.5 ; P_CAL_OCP_CPU_B_0_P.5 94.63,78.22 ; P_CAL_OCP_CPU_B_0_P.5 95.76,77.09 ; P_CAL_OCP_CPU_B_0_P.5 95.76,78.22 ; 246.19,48.45 P_SMA_BOT_2IN_DP_1.5 ; P_SMA_BOT_2IN_DP_1.5 247.31,49.58 ; P_SMA_BOT_2IN_DP_1.5 246.19,49.58 ; P_SMA_BOT_2IN_DP_1.5 247.31,48.45 ; P_SMA_TOP_2IN_DP_2.4 71.42,66.28 ; P_SMA_TOP_2IN_DP_2.4 70.29,66.28 ; P_SMA_TOP_2IN_DP_2.4 71.42,67.4 ; P_SMA_TOP_2IN_DP_2.4 70.29,67.4 ; 266.51,48.63 P_SMA_TOP_5IN_DP_2.3 ; P_SMA_TOP_5IN_DP_2.3 267.63,48.63 ; P_SMA_TOP_5IN_DP_2.3 266.51,47.5 ; P_SMA_TOP_5IN_DP_2.3 267.63,47.5 ; P_SMA_BOT_10IN_DP_1.3 247.31,4.07 ; P_SMA_BOT_10IN_DP_1.3 246.19,4.07 ; P_SMA_BOT_10IN_DP_1.3 247.31,5.19 ; P_SMA_BOT_10IN_DP_1.3 246.19,5.19 ; P_SMA_TOP_10IN_DP_2.3 267.63,18.54 ; P_SMA_TOP_10IN_DP_2.3 266.51,18.54 ; P_SMA_TOP_10IN_DP_2.3 266.51,19.67 ; P_SMA_TOP_10IN_DP_2.3 267.63,19.67 ; 82.25,82.52 P_CAL_OCP_CPU_B_0_N.4 ; P_CAL_OCP_CPU_B_0_N.4 83.38,81.39 ; P_CAL_OCP_CPU_B_0_N.4 83.38,82.52 ; P_CAL_OCP_CPU_B_0_N.4 82.25,81.39 ; P_SMA_BOT_2IN_DN_1.2 211.63,36.37 ; P_SMA_BOT_2IN_DN_1.2 211.63,37.5 ; P_SMA_BOT_2IN_DN_1.2 210.5,36.37 ; P_SMA_BOT_2IN_DN_1.2 210.5,37.5 ; 266.51,67.4 P_SMA_TOP_5IN_DN_2.4 ; P_SMA_TOP_5IN_DN_2.4 267.63,67.4 ; P_SMA_TOP_5IN_DN_2.4 266.51,66.28 ; P_SMA_TOP_5IN_DN_2.4 267.63,66.28 ; 97.98,77.09 P_CAL_OCP_CPU_B_0_P.4 ; P_CAL_OCP_CPU_B_0_P.4 99.11,78.22 ; P_CAL_OCP_CPU_B_0_P.4 99.11,77.09 ; P_CAL_OCP_CPU_B_0_P.4 97.98,78.22 ; 30.31,51.98 P_SMA_TOP_2IN_DN_1.5 ; P_SMA_TOP_2IN_DN_1.5 31.43,50.85 ; P_SMA_TOP_2IN_DN_1.5 30.31,50.85 ; P_SMA_TOP_2IN_DN_1.5 31.43,51.98 ; P_SMA_TOP_2IN_DN_1.4 31.43,48.63 ; P_SMA_TOP_2IN_DN_1.4 30.31,47.5 ; P_SMA_TOP_2IN_DN_1.4 30.31,48.63 ; P_SMA_TOP_2IN_DN_1.4 31.43,47.5 ; 30.31,67.4 P_SMA_TOP_2IN_DP_1.3 ; P_SMA_TOP_2IN_DP_1.3 31.43,67.4 ; P_SMA_TOP_2IN_DP_1.3 30.31,66.28 ; P_SMA_TOP_2IN_DP_1.3 31.43,66.28 ; 246.19,22.84 P_SMA_BOT_10IN_DN_1.4 ; P_SMA_BOT_10IN_DN_1.4 247.31,23.97 ; P_SMA_BOT_10IN_DN_1.4 246.19,23.97 ; P_SMA_BOT_10IN_DN_1.4 247.31,22.84 ; P_SMA_TOP_10IN_DP_2.5 263.33,23.02 ; P_SMA_TOP_10IN_DP_2.5 262.21,23.02 ; P_SMA_TOP_10IN_DP_2.5 263.33,21.89 ; P_SMA_TOP_10IN_DP_2.5 262.21,21.89 ; 266.51,21.89 P_SMA_TOP_10IN_DP_2.2 ; P_SMA_TOP_10IN_DP_2.2 267.63,23.02 ; P_SMA_TOP_10IN_DP_2.2 267.63,21.89 ; P_SMA_TOP_10IN_DP_2.2 266.51,23.02 ; 120.35,81.39 P_CAL_CPU_OCP_0_N1.4 ; P_CAL_CPU_OCP_0_N1.4 120.35,82.52 ; P_CAL_CPU_OCP_0_N1.4 121.48,81.39 ; P_CAL_CPU_OCP_0_N1.4 121.48,82.52 ; 123.51,33.02 P_SMA_BOT_5IN_DP_2.3 ; P_SMA_BOT_5IN_DP_2.3 124.63,33.02 ; P_SMA_BOT_5IN_DP_2.3 124.63,34.15 ; P_SMA_BOT_5IN_DP_2.3 123.51,34.15 ; 34.61,66.28 P_SMA_TOP_2IN_DP_1.4 ; P_SMA_TOP_2IN_DP_1.4 34.61,67.4 ; P_SMA_TOP_2IN_DP_1.4 35.73,67.4 ; P_SMA_TOP_2IN_DP_1.4 35.73,66.28 ; 34.61,37.32 P_SMA_TOP_10IN_DN_1.4 ; P_SMA_TOP_10IN_DN_1.4 34.61,38.45 ; P_SMA_TOP_10IN_DN_1.4 35.73,38.45 ; P_SMA_TOP_10IN_DN_1.4 35.73,37.32 ; 266.51,35.1 P_SMA_TOP_10IN_DN_2.5 ; P_SMA_TOP_10IN_DN_2.5 267.63,35.1 ; P_SMA_TOP_10IN_DN_2.5 266.51,33.97 ; P_SMA_TOP_10IN_DN_2.5 267.63,33.97 ; 206.2,48.45 P_SMA_BOT_2IN_DP_2.2 ; P_SMA_BOT_2IN_DP_2.2 207.33,48.45 ; P_SMA_BOT_2IN_DP_2.2 207.33,49.58 ; P_SMA_BOT_2IN_DP_2.2 206.2,49.58 ; 132.73,77.09 P_CAL_CPU_OCP_0_P1.5 ; P_CAL_CPU_OCP_0_P1.5 133.86,77.09 ; P_CAL_CPU_OCP_0_P1.5 133.86,78.22 ; P_CAL_CPU_OCP_0_P1.5 132.73,78.22 ; P_CAL_CPU_OCP_0_P1.2 133.86,81.39 ; P_CAL_CPU_OCP_0_P1.2 133.86,82.52 ; P_CAL_CPU_OCP_0_P1.2 132.73,81.39 ; P_CAL_CPU_OCP_0_P1.2 132.73,82.52 ; 70.29,48.63 P_SMA_TOP_2IN_DN_2.3 ; P_SMA_TOP_2IN_DN_2.3 71.42,47.5 ; P_SMA_TOP_2IN_DN_2.3 70.29,47.5 ; P_SMA_TOP_2IN_DN_2.3 71.42,48.63
  GD2 w0.254: P_SMA_BOT_2IN_DP_2.4 211.63,52.93 ; P_SMA_BOT_2IN_DP_2.4 210.5,51.8 ; P_SMA_BOT_2IN_DP_2.4 211.63,51.8 ; P_SMA_BOT_2IN_DP_2.4 210.5,52.93 ; P_SMA_BOT_2IN_DP_1.4 247.31,52.93 ; P_SMA_BOT_2IN_DP_1.4 246.19,52.93 ; P_SMA_BOT_2IN_DP_1.4 247.31,51.8 ; P_SMA_BOT_2IN_DP_1.4 246.19,51.8 ; P_SMA_TOP_2IN_DN_2.4 67.12,48.63 ; P_SMA_TOP_2IN_DN_2.4 67.12,47.5 ; P_SMA_TOP_2IN_DN_2.4 65.99,48.63 ; P_SMA_TOP_2IN_DN_2.4 65.99,47.5 ; P_SMA_TOP_5IN_DP_1.2 158.41,50.85 ; P_SMA_TOP_5IN_DP_1.2 158.41,51.98 ; P_SMA_TOP_5IN_DP_1.2 157.29,50.85 ; P_SMA_TOP_5IN_DP_1.2 157.29,51.98 ; P_SMA_BOT_5IN_DP_1.4 11.11,34.15 ; P_SMA_BOT_5IN_DP_1.4 11.11,33.02 ; P_SMA_BOT_5IN_DP_1.4 9.99,33.02 ; P_SMA_BOT_5IN_DP_1.4 9.99,34.15 ; P_SMA_TOP_5IN_DP_1.5 154.11,51.98 ; P_SMA_TOP_5IN_DP_1.5 152.99,51.98 ; P_SMA_TOP_5IN_DP_1.5 152.99,50.85 ; P_SMA_TOP_5IN_DP_1.5 154.11,50.85 ; 157.29,47.5 P_SMA_TOP_5IN_DP_1.3 ; P_SMA_TOP_5IN_DP_1.3 158.41,47.5 ; P_SMA_TOP_5IN_DP_1.3 158.41,48.63 ; P_SMA_TOP_5IN_DP_1.3 157.29,48.63 ; P_SMA_BOT_2IN_DN_1.5 207.33,36.37 ; P_SMA_BOT_2IN_DN_1.5 206.2,37.5 ; P_SMA_BOT_2IN_DN_1.5 207.33,37.5 ; P_SMA_BOT_2IN_DN_1.5 206.2,36.37 ; P_SMA_TOP_10IN_DN_2.3 263.33,38.45 ; P_SMA_TOP_10IN_DN_2.3 263.33,37.32 ; P_SMA_TOP_10IN_DN_2.3 262.21,38.45 ; P_SMA_TOP_10IN_DN_2.3 262.21,37.32 ; P_SMA_TOP_5IN_DN_2.5 267.63,64.05 ; P_SMA_TOP_5IN_DN_2.5 267.63,62.93 ; P_SMA_TOP_5IN_DN_2.5 266.51,64.05 ; P_SMA_TOP_5IN_DN_2.5 266.51,62.93 ; P_SMA_TOP_2IN_DN_2.3 71.42,47.5 ; P_SMA_TOP_2IN_DN_2.3 70.29,47.5 ; P_SMA_TOP_2IN_DN_2.3 71.42,48.63 ; P_SMA_TOP_2IN_DN_2.3 70.29,48.63 ; P_SMA_TOP_2IN_DP_1.5 35.73,62.93 ; P_SMA_TOP_2IN_DP_1.5 34.61,62.93 ; P_SMA_TOP_2IN_DP_1.5 35.73,64.05 ; P_SMA_TOP_2IN_DP_1.5 34.61,64.05 ; P_CAL_OCP_CPU_B_0_P.5 95.76,77.09 ; P_CAL_OCP_CPU_B_0_P.5 94.63,77.09 ; P_CAL_OCP_CPU_B_0_P.5 95.76,78.22 ; P_CAL_OCP_CPU_B_0_P.5 94.63,78.22 ; 206.2,34.15 P_SMA_BOT_2IN_DN_1.4 ; P_SMA_BOT_2IN_DN_1.4 207.33,33.02 ; P_SMA_BOT_2IN_DN_1.4 207.33,34.15 ; P_SMA_BOT_2IN_DN_1.4 206.2,33.02 ; 120.35,82.52 P_CAL_CPU_OCP_0_N1.4 ; P_CAL_CPU_OCP_0_N1.4 121.48,82.52 ; P_CAL_CPU_OCP_0_N1.4 121.48,81.39 ; P_CAL_CPU_OCP_0_N1.4 120.35,81.39 ; 157.29,64.05 P_SMA_TOP_5IN_DN_1.5 ; P_SMA_TOP_5IN_DN_1.5 158.41,62.93 ; P_SMA_TOP_5IN_DN_1.5 158.41,64.05 ; P_SMA_TOP_5IN_DN_1.5 157.29,62.93 ; P_SMA_TOP_2IN_DP_2.5 71.42,64.05 ; P_SMA_TOP_2IN_DP_2.5 70.29,64.05 ; P_SMA_TOP_2IN_DP_2.5 70.29,62.93 ; P_SMA_TOP_2IN_DP_2.5 71.42,62.93 ; P_SMA_TOP_10IN_DN_2.4 267.63,38.45 ; P_SMA_TOP_10IN_DN_2.4 266.51,37.32 ; P_SMA_TOP_10IN_DN_2.4 267.63,37.32 ; P_SMA_TOP_10IN_DN_2.4 266.51,38.45 ; 30.31,62.93 P_SMA_TOP_2IN_DP_1.2 ; P_SMA_TOP_2IN_DP_1.2 31.43,64.05 ; P_SMA_TOP_2IN_DP_1.2 30.31,64.05 ; P_SMA_TOP_2IN_DP_1.2 31.43,62.93 ; P_CAL_OCP_CPU_B_0_P.2 95.76,82.52 ; P_CAL_OCP_CPU_B_0_P.2 94.63,82.52 ; P_CAL_OCP_CPU_B_0_P.2 95.76,81.39 ; P_CAL_OCP_CPU_B_0_P.2 94.63,81.39 ; 210.5,37.5 P_SMA_BOT_2IN_DN_1.2 ; P_SMA_BOT_2IN_DN_1.2 210.5,36.37 ; P_SMA_BOT_2IN_DN_1.2 211.63,36.37 ; P_SMA_BOT_2IN_DN_1.2 211.63,37.5 ; 123.51,34.15 P_SMA_BOT_5IN_DP_2.3 ; P_SMA_BOT_5IN_DP_2.3 124.63,33.02 ; P_SMA_BOT_5IN_DP_2.3 123.51,33.02 ; P_SMA_BOT_5IN_DP_2.3 124.63,34.15 ; 152.99,66.28 P_SMA_TOP_5IN_DN_1.3 ; P_SMA_TOP_5IN_DN_1.3 154.11,67.4 ; P_SMA_TOP_5IN_DN_1.3 154.11,66.28 ; P_SMA_TOP_5IN_DN_1.3 152.99,67.4 ; 132.73,82.52 P_CAL_CPU_OCP_0_P1.2 ; P_CAL_CPU_OCP_0_P1.2 133.86,82.52 ; P_CAL_CPU_OCP_0_P1.2 132.73,81.39 ; P_CAL_CPU_OCP_0_P1.2 133.86,81.39 ; 123.51,37.5 P_SMA_BOT_5IN_DP_2.2 ; P_SMA_BOT_5IN_DP_2.2 123.51,36.37 ; P_SMA_BOT_5IN_DP_2.2 124.63,36.37 ; P_SMA_BOT_5IN_DP_2.2 124.63,37.5 ; P_SMA_TOP_10IN_DP_1.3 35.73,18.54 ; P_SMA_TOP_10IN_DP_1.3 34.61,19.67 ; P_SMA_TOP_10IN_DP_1.3 35.73,19.67 ; P_SMA_TOP_10IN_DP_1.3 34.61,18.54 ; P_SMA_TOP_5IN_DN_1.2 154.11,64.05 ; P_SMA_TOP_5IN_DN_1.2 152.99,64.05 ; P_SMA_TOP_5IN_DN_1.2 152.99,62.93 ; P_SMA_TOP_5IN_DN_1.2 154.11,62.93 ; 14.29,52.93 P_SMA_BOT_5IN_DN_1.4 ; P_SMA_BOT_5IN_DN_1.4 14.29,51.8 ; P_SMA_BOT_5IN_DN_1.4 15.41,52.93 ; P_SMA_BOT_5IN_DN_1.4 15.41,51.8 ; P_SMA_TOP_2IN_DP_2.2 67.12,64.05 ; P_SMA_TOP_2IN_DP_2.2 67.12,62.93 ; P_SMA_TOP_2IN_DP_2.2 65.99,64.05 ; P_SMA_TOP_2IN_DP_2.2 65.99,62.93 ; 14.29,4.07 P_SMA_BOT_10IN_DP_2.3 ; P_SMA_BOT_10IN_DP_2.3 14.29,5.19 ; P_SMA_BOT_10IN_DP_2.3 15.41,5.19 ; P_SMA_BOT_10IN_DP_2.3 15.41,4.07 ; P_SMA_BOT_5IN_DP_1.5 11.11,37.5 ; P_SMA_BOT_5IN_DP_1.5 9.99,36.37 ; P_SMA_BOT_5IN_DP_1.5 9.99,37.5 ; P_SMA_BOT_5IN_DP_1.5 11.11,36.37 ; P_SMA_BOT_2IN_DN_2.3 247.31,33.02 ; P_SMA_BOT_2IN_DN_2.3 247.31,34.15 ; P_SMA_BOT_2IN_DN_2.3 246.19,34.15 ; P_SMA_BOT_2IN_DN_2.3 246.19,33.02 ; P_SMA_TOP_10IN_DP_1.5 31.43,23.02 ; P_SMA_TOP_10IN_DP_1.5 30.31,23.02 ; P_SMA_TOP_10IN_DP_1.5 31.43,21.89 ; P_SMA_TOP_10IN_DP_1.5 30.31,21.89 ; P_SMA_TOP_10IN_DP_2.4 263.33,18.54 ; P_SMA_TOP_10IN_DP_2.4 262.21,19.67 ; P_SMA_TOP_10IN_DP_2.4 263.33,19.67 ; P_SMA_TOP_10IN_DP_2.4 262.21,18.54 ; P_SMA_BOT_2IN_DP_2.2 207.33,49.58 ; P_SMA_BOT_2IN_DP_2.2 206.2,49.58 ; P_SMA_BOT_2IN_DP_2.2 206.2,48.45 ; P_SMA_BOT_2IN_DP_2.2 207.33,48.45 ; 70.29,51.98 P_SMA_TOP_2IN_DN_2.2 ; P_SMA_TOP_2IN_DN_2.2 71.42,51.98 ; P_SMA_TOP_2IN_DN_2.2 71.42,50.85 ; P_SMA_TOP_2IN_DN_2.2 70.29,50.85 ; P_SMA_BOT_2IN_DN_1.3 211.63,33.02 ; P_SMA_BOT_2IN_DN_1.3 210.5,33.02 ; P_SMA_BOT_2IN_DN_1.3 210.5,34.15 ; P_SMA_BOT_2IN_DN_1.3 211.63,34.15 ; 241.89,49.58 P_SMA_BOT_2IN_DP_1.2 ; P_SMA_BOT_2IN_DP_1.2 241.89,48.45 ; P_SMA_BOT_2IN_DP_1.2 243.01,49.58 ; P_SMA_BOT_2IN_DP_1.2 243.01,48.45 ; 9.99,20.62 P_SMA_BOT_10IN_DN_2.2 ; P_SMA_BOT_10IN_DN_2.2 11.11,19.49 ; P_SMA_BOT_10IN_DN_2.2 11.11,20.62 ; P_SMA_BOT_10IN_DN_2.2 9.99,19.49 ; P_SMA_BOT_10IN_DP_1.2 247.31,7.42 ; P_SMA_BOT_10IN_DP_1.2 246.19,7.42 ; P_SMA_BOT_10IN_DP_1.2 246.19,8.54 ; P_SMA_BOT_10IN_DP_1.2 247.31,8.54 ; 266.51,23.02 P_SMA_TOP_10IN_DP_2.2 ; P_SMA_TOP_10IN_DP_2.2 266.51,21.89 ; P_SMA_TOP_10IN_DP_2.2 267.63,21.89 ; P_SMA_TOP_10IN_DP_2.2 267.63,23.02 ; P_SMA_BOT_5IN_DN_1.3 11.11,52.93 ; P_SMA_BOT_5IN_DN_1.3 9.99,51.8 ; P_SMA_BOT_5IN_DN_1.3 9.99,52.93 ; P_SMA_BOT_5IN_DN_1.3 11.11,51.8 ; P_SMA_TOP_10IN_DP_2.5 263.33,21.89 ; P_SMA_TOP_10IN_DP_2.5 262.21,23.02 ; P_SMA_TOP_10IN_DP_2.5 263.33,23.02 ; P_SMA_TOP_10IN_DP_2.5 262.21,21.89 ; P_SMA_TOP_2IN_DN_1.3 35.73,47.5 ; P_SMA_TOP_2IN_DN_1.3 35.73,48.63 ; P_SMA_TOP_2IN_DN_1.3 34.61,47.5 ; P_SMA_TOP_2IN_DN_1.3 34.61,48.63 ; 9.99,4.07 P_SMA_BOT_10IN_DP_2.4 ; P_SMA_BOT_10IN_DP_2.4 9.99,5.19 ; P_SMA_BOT_10IN_DP_2.4 11.11,5.19 ; P_SMA_BOT_10IN_DP_2.4 11.11,4.07 ; P_SMA_TOP_5IN_DP_2.4 263.33,47.5 ; P_SMA_TOP_5IN_DP_2.4 262.21,48.63 ; P_SMA_TOP_5IN_DP_2.4 263.33,48.63 ; P_SMA_TOP_5IN_DP_2.4 262.21,47.5 ; P_SMA_TOP_2IN_DP_2.4 71.42,66.28 ; P_SMA_TOP_2IN_DP_2.4 70.29,67.4 ; P_SMA_TOP_2IN_DP_2.4 71.42,67.4 ; P_SMA_TOP_2IN_DP_2.4 70.29,66.28 ; 123.7,81.39 P_CAL_CPU_OCP_0_N1.5 ; P_CAL_CPU_OCP_0_N1.5 124.83,81.39 ; P_CAL_CPU_OCP_0_N1.5 123.7,82.52 ; P_CAL_CPU_OCP_0_N1.5 124.83,82.52 ; P_SMA_TOP_10IN_DN_2.5 267.63,35.1 ; P_SMA_TOP_10IN_DN_2.5 266.51,33.97 ; P_SMA_TOP_10IN_DN_2.5 267.63,33.97 ; P_SMA_TOP_10IN_DN_2.5 266.51,35.1 ; P_SMA_TOP_2IN_DN_2.5 67.12,51.98 ; P_SMA_TOP_2IN_DN_2.5 65.99,51.98 ; P_SMA_TOP_2IN_DN_2.5 65.99,50.85 ; P_SMA_TOP_2IN_DN_2.5 67.12,50.85 ; 30.31,38.45 P_SMA_TOP_10IN_DN_1.3 ; P_SMA_TOP_10IN_DN_1.3 31.43,37.32 ; P_SMA_TOP_10IN_DN_1.3 31.43,38.45 ; P_SMA_TOP_10IN_DN_1.3 30.31,37.32 ; P_SMA_BOT_5IN_DN_1.5 15.41,48.45 ; P_SMA_BOT_5IN_DN_1.5 15.41,49.58 ; P_SMA_BOT_5IN_DN_1.5 14.29,48.45 ; P_SMA_BOT_5IN_DN_1.5 14.29,49.58 ; P_SMA_BOT_10IN_DN_1.3 243.01,22.84 ; P_SMA_BOT_10IN_DN_1.3 243.01,23.97 ; P_SMA_BOT_10IN_DN_1.3 241.89,23.97 ; P_SMA_BOT_10IN_DN_1.3 241.89,22.84 ; 206.2,51.8 P_SMA_BOT_2IN_DP_2.3 ; P_SMA_BOT_2IN_DP_2.3 206.2,52.93 ; P_SMA_BOT_2IN_DP_2.3 207.33,52.93 ; P_SMA_BOT_2IN_DP_2.3 207.33,51.8 ; P_SMA_BOT_2IN_DP_1.3 243.01,52.93 ; P_SMA_BOT_2IN_DP_1.3 241.89,51.8 ; P_SMA_BOT_2IN_DP_1.3 241.89,52.93 ; P_SMA_BOT_2IN_DP_1.3 243.01,51.8 ; P_SMA_TOP_10IN_DN_2.2 263.33,33.97 ; P_SMA_TOP_10IN_DN_2.2 262.21,35.1 ; P_SMA_TOP_10IN_DN_2.2 263.33,35.1 ; P_SMA_TOP_10IN_DN_2.2 262.21,33.97 ; P_SMA_TOP_5IN_DP_2.3 267.63,48.63 ; P_SMA_TOP_5IN_DP_2.3 267.63,47.5 ; P_SMA_TOP_5IN_DP_2.3 266.51,47.5 ; P_SMA_TOP_5IN_DP_2.3 266.51,48.63 ; P_SMA_BOT_10IN_DN_1.2 243.01,20.62 ; P_SMA_BOT_10IN_DN_1.2 241.89,20.62 ; P_SMA_BOT_10IN_DN_1.2 241.89,19.49 ; P_SMA_BOT_10IN_DN_1.2 243.01,19.49 ; P_SMA_BOT_5IN_DN_1.2 11.11,48.45 ; P_SMA_BOT_5IN_DN_1.2 11.11,49.58 ; P_SMA_BOT_5IN_DN_1.2 9.99,48.45 ; P_SMA_BOT_5IN_DN_1.2 9.99,49.58 ; 123.7,77.09 P_CAL_CPU_OCP_0_N1.2 ; P_CAL_CPU_OCP_0_N1.2 124.83,77.09 ; P_CAL_CPU_OCP_0_N1.2 124.83,78.22 ; P_CAL_CPU_OCP_0_N1.2 123.7,78.22 ; P_SMA_BOT_10IN_DP_1.4 243.01,4.07 ; P_SMA_BOT_10IN_DP_1.4 241.89,5.19 ; P_SMA_BOT_10IN_DP_1.4 241.89,4.07 ; P_SMA_BOT_10IN_DP_1.4 243.01,5.19 ; P_SMA_BOT_5IN_DN_2.4 124.63,52.93 ; P_SMA_BOT_5IN_DN_2.4 124.63,51.8 ; P_SMA_BOT_5IN_DN_2.4 123.51,52.93 ; P_SMA_BOT_5IN_DN_2.4 123.51,51.8 ; 9.99,22.84 P_SMA_BOT_10IN_DN_2.3 ; P_SMA_BOT_10IN_DN_2.3 11.11,22.84 ; P_SMA_BOT_10IN_DN_2.3 9.99,23.97 ; P_SMA_BOT_10IN_DN_2.3 11.11,23.97 ; 14.29,20.62 P_SMA_BOT_10IN_DN_2.5 ; P_SMA_BOT_10IN_DN_2.5 15.41,20.62 ; P_SMA_BOT_10IN_DN_2.5 14.29,19.49 ; P_SMA_BOT_10IN_DN_2.5 15.41,19.49 ; 152.99,48.63 P_SMA_TOP_5IN_DP_1.4 ; P_SMA_TOP_5IN_DP_1.4 152.99,47.5 ; P_SMA_TOP_5IN_DP_1.4 154.11,47.5 ; P_SMA_TOP_5IN_DP_1.4 154.11,48.63 ; 119.21,51.8 P_SMA_BOT_5IN_DN_2.3 ; P_SMA_BOT_5IN_DN_2.3 119.21,52.93 ; P_SMA_BOT_5IN_DN_2.3 120.33,52.93 ; P_SMA_BOT_5IN_DN_2.3 120.33,51.8 ; 30.31,67.4 P_SMA_TOP_2IN_DP_1.3 ; P_SMA_TOP_2IN_DP_1.3 31.43,66.28 ; P_SMA_TOP_2IN_DP_1.3 31.43,67.4 ; P_SMA_TOP_2IN_DP_1.3 30.31,66.28 ; P_SMA_BOT_5IN_DP_1.2 15.41,37.5 ; P_SMA_BOT_5IN_DP_1.2 14.29,37.5 ; P_SMA_BOT_5IN_DP_1.2 14.29,36.37 ; P_SMA_BOT_5IN_DP_1.2 15.41,36.37 ; 119.21,37.5 P_SMA_BOT_5IN_DP_2.5 ; P_SMA_BOT_5IN_DP_2.5 120.33,37.5 ; P_SMA_BOT_5IN_DP_2.5 120.33,36.37 ; P_SMA_BOT_5IN_DP_2.5 119.21,36.37 ; P_SMA_TOP_10IN_DP_2.3 267.63,18.54 ; P_SMA_TOP_10IN_DP_2.3 266.51,18.54 ; P_SMA_TOP_10IN_DP_2.3 267.63,19.67 ; P_SMA_TOP_10IN_DP_2.3 266.51,19.67 ; P_CAL_OCP_CPU_B_0_N.5 86.73,82.52 ; P_CAL_OCP_CPU_B_0_N.5 85.6,81.39 ; P_CAL_OCP_CPU_B_0_N.5 86.73,81.39 ; P_CAL_OCP_CPU_B_0_N.5 85.6,82.52 ; 246.19,48.45 P_SMA_BOT_2IN_DP_1.5 ; P_SMA_BOT_2IN_DP_1.5 246.19,49.58 ; P_SMA_BOT_2IN_DP_1.5 247.31,48.45 ; P_SMA_BOT_2IN_DP_1.5 247.31,49.58 ; P_SMA_TOP_10IN_DN_1.2 31.43,33.97 ; P_SMA_TOP_10IN_DN_1.2 30.31,33.97 ; P_SMA_TOP_10IN_DN_1.2 30.31,35.1 ; P_SMA_TOP_10IN_DN_1.2 31.43,35.1 ; 65.99,66.28 P_SMA_TOP_2IN_DP_2.3 ; P_SMA_TOP_2IN_DP_2.3 65.99,67.4 ; P_SMA_TOP_2IN_DP_2.3 67.12,66.28 ; P_SMA_TOP_2IN_DP_2.3 67.12,67.4 ; 241.89,7.42 P_SMA_BOT_10IN_DP_1.5 ; P_SMA_BOT_10IN_DP_1.5 241.89,8.54 ; P_SMA_BOT_10IN_DP_1.5 243.01,8.54 ; P_SMA_BOT_10IN_DP_1.5 243.01,7.42 ; P_SMA_TOP_5IN_DP_2.5 263.33,50.85 ; P_SMA_TOP_5IN_DP_2.5 263.33,51.98 ; P_SMA_TOP_5IN_DP_2.5 262.21,50.85 ; P_SMA_TOP_5IN_DP_2.5 262.21,51.98 ; P_SMA_TOP_2IN_DN_1.5 31.43,50.85 ; P_SMA_TOP_2IN_DN_1.5 30.31,51.98 ; P_SMA_TOP_2IN_DN_1.5 30.31,50.85 ; P_SMA_TOP_2IN_DN_1.5 31.43,51.98 ; 120.35,77.09 P_CAL_CPU_OCP_0_N1.3 ; P_CAL_CPU_OCP_0_N1.3 120.35,78.22 ; P_CAL_CPU_OCP_0_N1.3 121.48,78.22 ; P_CAL_CPU_OCP_0_N1.3 121.48,77.09 ; 132.73,77.09 P_CAL_CPU_OCP_0_P1.5 ; P_CAL_CPU_OCP_0_P1.5 133.86,78.22 ; P_CAL_CPU_OCP_0_P1.5 133.86,77.09 ; P_CAL_CPU_OCP_0_P1.5 132.73,78.22 ; 34.61,35.1 P_SMA_TOP_10IN_DN_1.5 ; P_SMA_TOP_10IN_DN_1.5 34.61,33.97 ; P_SMA_TOP_10IN_DN_1.5 35.73,33.97 ; P_SMA_TOP_10IN_DN_1.5 35.73,35.1 ; 97.98,81.39 P_CAL_OCP_CPU_B_0_P.3 ; P_CAL_OCP_CPU_B_0_P.3 99.11,82.52 ; P_CAL_OCP_CPU_B_0_P.3 97.98,82.52 ; P_CAL_OCP_CPU_B_0_P.3 99.11,81.39 ; P_SMA_BOT_2IN_DN_2.5 243.01,36.37 ; P_SMA_BOT_2IN_DN_2.5 243.01,37.5 ; P_SMA_BOT_2IN_DN_2.5 241.89,36.37 ; P_SMA_BOT_2IN_DN_2.5 241.89,37.5 ; 30.31,47.5 P_SMA_TOP_2IN_DN_1.4 ; P_SMA_TOP_2IN_DN_1.4 30.31,48.63 ; P_SMA_TOP_2IN_DN_1.4 31.43,47.5 ; P_SMA_TOP_2IN_DN_1.4 31.43,48.63 ; 97.98,78.22 P_CAL_OCP_CPU_B_0_P.4 ; P_CAL_OCP_CPU_B_0_P.4 99.11,77.09 ; P_CAL_OCP_CPU_B_0_P.4 97.98,77.09 ; P_CAL_OCP_CPU_B_0_P.4 99.11,78.22 ; 14.29,23.97 P_SMA_BOT_10IN_DN_2.4 ; P_SMA_BOT_10IN_DN_2.4 15.41,23.97 ; P_SMA_BOT_10IN_DN_2.4 14.29,22.84 ; P_SMA_BOT_10IN_DN_2.4 15.41,22.84 ; 262.21,66.28 P_SMA_TOP_5IN_DN_2.3 ; P_SMA_TOP_5IN_DN_2.3 262.21,67.4 ; P_SMA_TOP_5IN_DN_2.3 263.33,66.28 ; P_SMA_TOP_5IN_DN_2.3 263.33,67.4 ; 34.61,37.32 P_SMA_TOP_10IN_DN_1.4 ; P_SMA_TOP_10IN_DN_1.4 34.61,38.45 ; P_SMA_TOP_10IN_DN_1.4 35.73,38.45 ; P_SMA_TOP_10IN_DN_1.4 35.73,37.32 ; 136.08,77.09 P_CAL_CPU_OCP_0_P1.4 ; P_CAL_CPU_OCP_0_P1.4 137.21,78.22 ; P_CAL_CPU_OCP_0_P1.4 137.21,77.09 ; P_CAL_CPU_OCP_0_P1.4 136.08,78.22 ; 136.08,81.39 P_CAL_CPU_OCP_0_P1.3 ; P_CAL_CPU_OCP_0_P1.3 137.21,81.39 ; P_CAL_CPU_OCP_0_P1.3 136.08,82.52 ; P_CAL_CPU_OCP_0_P1.3 137.21,82.52 ; 266.51,66.28 P_SMA_TOP_5IN_DN_2.4 ; P_SMA_TOP_5IN_DN_2.4 267.63,67.4 ; P_SMA_TOP_5IN_DN_2.4 267.63,66.28 ; P_SMA_TOP_5IN_DN_2.4 266.51,67.4 ; 82.25,81.39 P_CAL_OCP_CPU_B_0_N.4 ; P_CAL_OCP_CPU_B_0_N.4 83.38,82.52 ; P_CAL_OCP_CPU_B_0_N.4 83.38,81.39 ; P_CAL_OCP_CPU_B_0_N.4 82.25,82.52 ; P_SMA_BOT_10IN_DN_1.4 247.31,22.84 ; P_SMA_BOT_10IN_DN_1.4 246.19,22.84 ; P_SMA_BOT_10IN_DN_1.4 247.31,23.97 ; P_SMA_BOT_10IN_DN_1.4 246.19,23.97 ; 246.19,5.19 P_SMA_BOT_10IN_DP_1.3 ; P_SMA_BOT_10IN_DP_1.3 247.31,5.19 ; P_SMA_BOT_10IN_DP_1.3 246.19,4.07 ; P_SMA_BOT_10IN_DP_1.3 247.31,4.07 ; 246.19,37.5 P_SMA_BOT_2IN_DN_2.2 ; P_SMA_BOT_2IN_DN_2.2 247.31,36.37 ; P_SMA_BOT_2IN_DN_2.2 247.31,37.5 ; P_SMA_BOT_2IN_DN_2.2 246.19,36.37 ; P_CAL_OCP_CPU_B_0_N.2 86.73,77.09 ; P_CAL_OCP_CPU_B_0_N.2 85.6,78.22 ; P_CAL_OCP_CPU_B_0_N.2 86.73,78.22 ; P_CAL_OCP_CPU_B_0_N.2 85.6,77.09 ; P_SMA_TOP_2IN_DP_1.4 35.73,66.28 ; P_SMA_TOP_2IN_DP_1.4 34.61,67.4 ; P_SMA_TOP_2IN_DP_1.4 34.61,66.28 ; P_SMA_TOP_2IN_DP_1.4 35.73,67.4 ; 119.21,34.15 P_SMA_BOT_5IN_DP_2.4 ; P_SMA_BOT_5IN_DP_2.4 119.21,33.02 ; P_SMA_BOT_5IN_DP_2.4 120.33,33.02 ; P_SMA_BOT_5IN_DP_2.4 120.33,34.15 ; P_CAL_OCP_CPU_B_0_N.3 83.38,78.22 ; P_CAL_OCP_CPU_B_0_N.3 83.38,77.09 ; P_CAL_OCP_CPU_B_0_N.3 82.25,78.22 ; P_CAL_OCP_CPU_B_0_N.3 82.25,77.09 ; 262.21,62.93 P_SMA_TOP_5IN_DN_2.2 ; P_SMA_TOP_5IN_DN_2.2 262.21,64.05 ; P_SMA_TOP_5IN_DN_2.2 263.33,62.93 ; P_SMA_TOP_5IN_DN_2.2 263.33,64.05 ; P_SMA_TOP_5IN_DN_1.4 158.41,66.28 ; P_SMA_TOP_5IN_DN_1.4 157.29,66.28 ; P_SMA_TOP_5IN_DN_1.4 157.29,67.4 ; P_SMA_TOP_5IN_DN_1.4 158.41,67.4 ; 241.89,34.15 P_SMA_BOT_2IN_DN_2.4 ; P_SMA_BOT_2IN_DN_2.4 241.89,33.02 ; P_SMA_BOT_2IN_DN_2.4 243.01,34.15 ; P_SMA_BOT_2IN_DN_2.4 243.01,33.02 ; P_SMA_BOT_5IN_DP_1.3 15.41,34.15 ; P_SMA_BOT_5IN_DP_1.3 15.41,33.02 ; P_SMA_BOT_5IN_DP_1.3 14.29,33.02 ; P_SMA_BOT_5IN_DP_1.3 14.29,34.15 ; 266.51,50.85 P_SMA_TOP_5IN_DP_2.2 ; P_SMA_TOP_5IN_DP_2.2 267.63,51.98 ; P_SMA_TOP_5IN_DP_2.2 266.51,51.98 ; P_SMA_TOP_5IN_DP_2.2 267.63,50.85 ; P_SMA_BOT_5IN_DN_2.2 120.33,48.45 ; P_SMA_BOT_5IN_DN_2.2 120.33,49.58 ; P_SMA_BOT_5IN_DN_2.2 119.21,48.45 ; P_SMA_BOT_5IN_DN_2.2 119.21,49.58 ; 246.19,20.62 P_SMA_BOT_10IN_DN_1.5 ; P_SMA_BOT_10IN_DN_1.5 247.31,20.62 ; P_SMA_BOT_10IN_DN_1.5 247.31,19.49 ; P_SMA_BOT_10IN_DN_1.5 246.19,19.49 ; 34.61,23.02 P_SMA_TOP_10IN_DP_1.2 ; P_SMA_TOP_10IN_DP_1.2 34.61,21.89 ; P_SMA_TOP_10IN_DP_1.2 35.73,23.02 ; P_SMA_TOP_10IN_DP_1.2 35.73,21.89 ; 210.5,49.58 P_SMA_BOT_2IN_DP_2.5 ; P_SMA_BOT_2IN_DP_2.5 211.63,49.58 ; P_SMA_BOT_2IN_DP_2.5 211.63,48.45 ; P_SMA_BOT_2IN_DP_2.5 210.5,48.45 ; P_SMA_TOP_2IN_DN_1.2 35.73,50.85 ; P_SMA_TOP_2IN_DN_1.2 34.61,50.85 ; P_SMA_TOP_2IN_DN_1.2 34.61,51.98 ; P_SMA_TOP_2IN_DN_1.2 35.73,51.98 ; P_SMA_BOT_5IN_DN_2.5 124.63,49.58 ; P_SMA_BOT_5IN_DN_2.5 123.51,48.45 ; P_SMA_BOT_5IN_DN_2.5 124.63,48.45 ; P_SMA_BOT_5IN_DN_2.5 123.51,49.58 ; 9.99,7.42 P_SMA_BOT_10IN_DP_2.5 ; P_SMA_BOT_10IN_DP_2.5 11.11,7.42 ; P_SMA_BOT_10IN_DP_2.5 11.11,8.54 ; P_SMA_BOT_10IN_DP_2.5 9.99,8.54 ; P_SMA_BOT_10IN_DP_2.2 15.41,7.42 ; P_SMA_BOT_10IN_DP_2.2 15.41,8.54 ; P_SMA_BOT_10IN_DP_2.2 14.29,7.42 ; P_SMA_BOT_10IN_DP_2.2 14.29,8.54 ; 30.31,18.54 P_SMA_TOP_10IN_DP_1.4 ; P_SMA_TOP_10IN_DP_1.4 31.43,19.67 ; P_SMA_TOP_10IN_DP_1.4 30.31,19.67 ; P_SMA_TOP_10IN_DP_1.4 31.43,18.54
  GD3 w0.254: P_SMA_TOP_10IN_DN_1.2 31.43,33.97 ; P_SMA_TOP_10IN_DN_1.2 30.31,33.97 ; P_SMA_TOP_10IN_DN_1.2 31.43,35.1 ; P_SMA_TOP_10IN_DN_1.2 30.31,35.1 ; P_SMA_TOP_10IN_DP_2.2 267.63,21.89 ; P_SMA_TOP_10IN_DP_2.2 266.51,21.89 ; P_SMA_TOP_10IN_DP_2.2 267.63,23.02 ; P_SMA_TOP_10IN_DP_2.2 266.51,23.02 ; 266.51,35.1 P_SMA_TOP_10IN_DN_2.5 ; P_SMA_TOP_10IN_DN_2.5 266.51,33.97 ; P_SMA_TOP_10IN_DN_2.5 267.63,35.1 ; P_SMA_TOP_10IN_DN_2.5 267.63,33.97 ; 246.19,5.19 P_SMA_BOT_10IN_DP_1.3 ; P_SMA_BOT_10IN_DP_1.3 246.19,4.07 ; P_SMA_BOT_10IN_DP_1.3 247.31,5.19 ; P_SMA_BOT_10IN_DP_1.3 247.31,4.07 ; P_CAL_OCP_CPU_B_0_N.5 86.73,82.52 ; P_CAL_OCP_CPU_B_0_N.5 85.6,82.52 ; P_CAL_OCP_CPU_B_0_N.5 85.6,81.39 ; P_CAL_OCP_CPU_B_0_N.5 86.73,81.39 ; P_SMA_BOT_2IN_DP_1.4 247.31,51.8 ; P_SMA_BOT_2IN_DP_1.4 246.19,51.8 ; P_SMA_BOT_2IN_DP_1.4 247.31,52.93 ; P_SMA_BOT_2IN_DP_1.4 246.19,52.93 ; P_SMA_BOT_2IN_DN_2.4 243.01,34.15 ; P_SMA_BOT_2IN_DN_2.4 241.89,34.15 ; P_SMA_BOT_2IN_DN_2.4 243.01,33.02 ; P_SMA_BOT_2IN_DN_2.4 241.89,33.02 ; P_SMA_BOT_5IN_DN_1.3 11.11,52.93 ; P_SMA_BOT_5IN_DN_1.3 9.99,51.8 ; P_SMA_BOT_5IN_DN_1.3 9.99,52.93 ; P_SMA_BOT_5IN_DN_1.3 11.11,51.8 ; P_SMA_TOP_2IN_DP_1.2 31.43,64.05 ; P_SMA_TOP_2IN_DP_1.2 31.43,62.93 ; P_SMA_TOP_2IN_DP_1.2 30.31,64.05 ; P_SMA_TOP_2IN_DP_1.2 30.31,62.93 ; P_SMA_TOP_10IN_DP_1.4 31.43,19.67 ; P_SMA_TOP_10IN_DP_1.4 30.31,19.67 ; P_SMA_TOP_10IN_DP_1.4 31.43,18.54 ; P_SMA_TOP_10IN_DP_1.4 30.31,18.54 ; 152.99,64.05 P_SMA_TOP_5IN_DN_1.2 ; P_SMA_TOP_5IN_DN_1.2 152.99,62.93 ; P_SMA_TOP_5IN_DN_1.2 154.11,62.93 ; P_SMA_TOP_5IN_DN_1.2 154.11,64.05 ; P_SMA_BOT_2IN_DP_1.5 247.31,49.58 ; P_SMA_BOT_2IN_DP_1.5 246.19,48.45 ; P_SMA_BOT_2IN_DP_1.5 247.31,48.45 ; P_SMA_BOT_2IN_DP_1.5 246.19,49.58 ; 123.51,37.5 P_SMA_BOT_5IN_DP_2.2 ; P_SMA_BOT_5IN_DP_2.2 124.63,36.37 ; P_SMA_BOT_5IN_DP_2.2 124.63,37.5 ; P_SMA_BOT_5IN_DP_2.2 123.51,36.37 ; P_SMA_TOP_2IN_DP_1.5 35.73,62.93 ; P_SMA_TOP_2IN_DP_1.5 35.73,64.05 ; P_SMA_TOP_2IN_DP_1.5 34.61,64.05 ; P_SMA_TOP_2IN_DP_1.5 34.61,62.93 ; 14.29,51.8 P_SMA_BOT_5IN_DN_1.4 ; P_SMA_BOT_5IN_DN_1.4 15.41,52.93 ; P_SMA_BOT_5IN_DN_1.4 14.29,52.93 ; P_SMA_BOT_5IN_DN_1.4 15.41,51.8 ; 30.31,66.28 P_SMA_TOP_2IN_DP_1.3 ; P_SMA_TOP_2IN_DP_1.3 31.43,66.28 ; P_SMA_TOP_2IN_DP_1.3 30.31,67.4 ; P_SMA_TOP_2IN_DP_1.3 31.43,67.4 ; P_SMA_TOP_10IN_DN_1.4 35.73,38.45 ; P_SMA_TOP_10IN_DN_1.4 35.73,37.32 ; P_SMA_TOP_10IN_DN_1.4 34.61,38.45 ; P_SMA_TOP_10IN_DN_1.4 34.61,37.32 ; P_CAL_CPU_OCP_0_P1.2 133.86,82.52 ; P_CAL_CPU_OCP_0_P1.2 132.73,82.52 ; P_CAL_CPU_OCP_0_P1.2 133.86,81.39 ; P_CAL_CPU_OCP_0_P1.2 132.73,81.39 ; 34.61,50.85 P_SMA_TOP_2IN_DN_1.2 ; P_SMA_TOP_2IN_DN_1.2 35.73,51.98 ; P_SMA_TOP_2IN_DN_1.2 35.73,50.85 ; P_SMA_TOP_2IN_DN_1.2 34.61,51.98 ; P_CAL_CPU_OCP_0_N1.4 121.48,82.52 ; P_CAL_CPU_OCP_0_N1.4 121.48,81.39 ; P_CAL_CPU_OCP_0_N1.4 120.35,81.39 ; P_CAL_CPU_OCP_0_N1.4 120.35,82.52 ; P_SMA_BOT_2IN_DN_1.2 211.63,37.5 ; P_SMA_BOT_2IN_DN_1.2 211.63,36.37 ; P_SMA_BOT_2IN_DN_1.2 210.5,37.5 ; P_SMA_BOT_2IN_DN_1.2 210.5,36.37 ; 136.08,78.22 P_CAL_CPU_OCP_0_P1.4 ; P_CAL_CPU_OCP_0_P1.4 136.08,77.09 ; P_CAL_CPU_OCP_0_P1.4 137.21,77.09 ; P_CAL_CPU_OCP_0_P1.4 137.21,78.22 ; P_SMA_BOT_10IN_DN_2.2 11.11,19.49 ; P_SMA_BOT_10IN_DN_2.2 9.99,19.49 ; P_SMA_BOT_10IN_DN_2.2 11.11,20.62 ; P_SMA_BOT_10IN_DN_2.2 9.99,20.62 ; P_SMA_BOT_2IN_DP_2.2 207.33,49.58 ; P_SMA_BOT_2IN_DP_2.2 206.2,49.58 ; P_SMA_BOT_2IN_DP_2.2 206.2,48.45 ; P_SMA_BOT_2IN_DP_2.2 207.33,48.45 ; 119.21,51.8 P_SMA_BOT_5IN_DN_2.3 ; P_SMA_BOT_5IN_DN_2.3 119.21,52.93 ; P_SMA_BOT_5IN_DN_2.3 120.33,51.8 ; P_SMA_BOT_5IN_DN_2.3 120.33,52.93 ; P_SMA_TOP_5IN_DN_1.4 158.41,67.4 ; P_SMA_TOP_5IN_DN_1.4 158.41,66.28 ; P_SMA_TOP_5IN_DN_1.4 157.29,67.4 ; P_SMA_TOP_5IN_DN_1.4 157.29,66.28 ; P_SMA_BOT_2IN_DN_1.3 211.63,33.02 ; P_SMA_BOT_2IN_DN_1.3 210.5,34.15 ; P_SMA_BOT_2IN_DN_1.3 210.5,33.02 ; P_SMA_BOT_2IN_DN_1.3 211.63,34.15 ; 266.51,51.98 P_SMA_TOP_5IN_DP_2.2 ; P_SMA_TOP_5IN_DP_2.2 267.63,50.85 ; P_SMA_TOP_5IN_DP_2.2 266.51,50.85 ; P_SMA_TOP_5IN_DP_2.2 267.63,51.98 ; P_SMA_TOP_2IN_DN_1.3 35.73,48.63 ; P_SMA_TOP_2IN_DN_1.3 34.61,47.5 ; P_SMA_TOP_2IN_DN_1.3 35.73,47.5 ; P_SMA_TOP_2IN_DN_1.3 34.61,48.63 ; P_SMA_TOP_5IN_DN_2.5 267.63,64.05 ; P_SMA_TOP_5IN_DN_2.5 266.51,64.05 ; P_SMA_TOP_5IN_DN_2.5 266.51,62.93 ; P_SMA_TOP_5IN_DN_2.5 267.63,62.93 ; P_SMA_TOP_10IN_DN_2.4 267.63,38.45 ; P_SMA_TOP_10IN_DN_2.4 266.51,38.45 ; P_SMA_TOP_10IN_DN_2.4 266.51,37.32 ; P_SMA_TOP_10IN_DN_2.4 267.63,37.32 ; P_SMA_TOP_5IN_DP_1.3 158.41,47.5 ; P_SMA_TOP_5IN_DP_1.3 158.41,48.63 ; P_SMA_TOP_5IN_DP_1.3 157.29,48.63 ; P_SMA_TOP_5IN_DP_1.3 157.29,47.5 ; 65.99,66.28 P_SMA_TOP_2IN_DP_2.3 ; P_SMA_TOP_2IN_DP_2.3 67.12,67.4 ; P_SMA_TOP_2IN_DP_2.3 65.99,67.4 ; P_SMA_TOP_2IN_DP_2.3 67.12,66.28 ; 262.21,23.02 P_SMA_TOP_10IN_DP_2.5 ; P_SMA_TOP_10IN_DP_2.5 263.33,23.02 ; P_SMA_TOP_10IN_DP_2.5 262.21,21.89 ; P_SMA_TOP_10IN_DP_2.5 263.33,21.89 ; 152.99,67.4 P_SMA_TOP_5IN_DN_1.3 ; P_SMA_TOP_5IN_DN_1.3 152.99,66.28 ; P_SMA_TOP_5IN_DN_1.3 154.11,67.4 ; P_SMA_TOP_5IN_DN_1.3 154.11,66.28 ; 206.2,37.5 P_SMA_BOT_2IN_DN_1.5 ; P_SMA_BOT_2IN_DN_1.5 206.2,36.37 ; P_SMA_BOT_2IN_DN_1.5 207.33,36.37 ; P_SMA_BOT_2IN_DN_1.5 207.33,37.5 ; 14.29,33.02 P_SMA_BOT_5IN_DP_1.3 ; P_SMA_BOT_5IN_DP_1.3 15.41,34.15 ; P_SMA_BOT_5IN_DP_1.3 14.29,34.15 ; P_SMA_BOT_5IN_DP_1.3 15.41,33.02 ; P_SMA_BOT_10IN_DP_1.2 247.31,7.42 ; P_SMA_BOT_10IN_DP_1.2 247.31,8.54 ; P_SMA_BOT_10IN_DP_1.2 246.19,7.42 ; P_SMA_BOT_10IN_DP_1.2 246.19,8.54 ; 123.51,34.15 P_SMA_BOT_5IN_DP_2.3 ; P_SMA_BOT_5IN_DP_2.3 123.51,33.02 ; P_SMA_BOT_5IN_DP_2.3 124.63,33.02 ; P_SMA_BOT_5IN_DP_2.3 124.63,34.15 ; 123.7,81.39 P_CAL_CPU_OCP_0_N1.5 ; P_CAL_CPU_OCP_0_N1.5 124.83,81.39 ; P_CAL_CPU_OCP_0_N1.5 124.83,82.52 ; P_CAL_CPU_OCP_0_N1.5 123.7,82.52 ; 266.51,19.67 P_SMA_TOP_10IN_DP_2.3 ; P_SMA_TOP_10IN_DP_2.3 267.63,18.54 ; P_SMA_TOP_10IN_DP_2.3 266.51,18.54 ; P_SMA_TOP_10IN_DP_2.3 267.63,19.67 ; P_SMA_BOT_5IN_DP_1.4 11.11,33.02 ; P_SMA_BOT_5IN_DP_1.4 9.99,33.02 ; P_SMA_BOT_5IN_DP_1.4 9.99,34.15 ; P_SMA_BOT_5IN_DP_1.4 11.11,34.15 ; P_CAL_OCP_CPU_B_0_N.4 83.38,82.52 ; P_CAL_OCP_CPU_B_0_N.4 82.25,81.39 ; P_CAL_OCP_CPU_B_0_N.4 83.38,81.39 ; P_CAL_OCP_CPU_B_0_N.4 82.25,82.52 ; 152.99,50.85 P_SMA_TOP_5IN_DP_1.5 ; P_SMA_TOP_5IN_DP_1.5 154.11,51.98 ; P_SMA_TOP_5IN_DP_1.5 152.99,51.98 ; P_SMA_TOP_5IN_DP_1.5 154.11,50.85 ; 266.51,48.63 P_SMA_TOP_5IN_DP_2.3 ; P_SMA_TOP_5IN_DP_2.3 267.63,47.5 ; P_SMA_TOP_5IN_DP_2.3 267.63,48.63 ; P_SMA_TOP_5IN_DP_2.3 266.51,47.5 ; P_SMA_BOT_10IN_DP_1.4 243.01,5.19 ; P_SMA_BOT_10IN_DP_1.4 241.89,4.07 ; P_SMA_BOT_10IN_DP_1.4 241.89,5.19 ; P_SMA_BOT_10IN_DP_1.4 243.01,4.07 ; P_SMA_TOP_2IN_DP_2.5 71.42,64.05 ; P_SMA_TOP_2IN_DP_2.5 70.29,64.05 ; P_SMA_TOP_2IN_DP_2.5 70.29,62.93 ; P_SMA_TOP_2IN_DP_2.5 71.42,62.93 ; 14.29,7.42 P_SMA_BOT_10IN_DP_2.2 ; P_SMA_BOT_10IN_DP_2.2 14.29,8.54 ; P_SMA_BOT_10IN_DP_2.2 15.41,7.42 ; P_SMA_BOT_10IN_DP_2.2 15.41,8.54 ; 241.89,7.42 P_SMA_BOT_10IN_DP_1.5 ; P_SMA_BOT_10IN_DP_1.5 241.89,8.54 ; P_SMA_BOT_10IN_DP_1.5 243.01,7.42 ; P_SMA_BOT_10IN_DP_1.5 243.01,8.54 ; 97.98,81.39 P_CAL_OCP_CPU_B_0_P.3 ; P_CAL_OCP_CPU_B_0_P.3 99.11,81.39 ; P_CAL_OCP_CPU_B_0_P.3 99.11,82.52 ; P_CAL_OCP_CPU_B_0_P.3 97.98,82.52 ; P_SMA_TOP_2IN_DN_1.4 31.43,47.5 ; P_SMA_TOP_2IN_DN_1.4 30.31,48.63 ; P_SMA_TOP_2IN_DN_1.4 31.43,48.63 ; P_SMA_TOP_2IN_DN_1.4 30.31,47.5 ; 210.5,48.45 P_SMA_BOT_2IN_DP_2.5 ; P_SMA_BOT_2IN_DP_2.5 211.63,48.45 ; P_SMA_BOT_2IN_DP_2.5 211.63,49.58 ; P_SMA_BOT_2IN_DP_2.5 210.5,49.58 ; P_SMA_BOT_10IN_DN_2.4 15.41,23.97 ; P_SMA_BOT_10IN_DN_2.4 15.41,22.84 ; P_SMA_BOT_10IN_DN_2.4 14.29,22.84 ; P_SMA_BOT_10IN_DN_2.4 14.29,23.97 ; 152.99,47.5 P_SMA_TOP_5IN_DP_1.4 ; P_SMA_TOP_5IN_DP_1.4 152.99,48.63 ; P_SMA_TOP_5IN_DP_1.4 154.11,47.5 ; P_SMA_TOP_5IN_DP_1.4 154.11,48.63 ; P_SMA_TOP_10IN_DN_1.5 35.73,35.1 ; P_SMA_TOP_10IN_DN_1.5 34.61,35.1 ; P_SMA_TOP_10IN_DN_1.5 34.61,33.97 ; P_SMA_TOP_10IN_DN_1.5 35.73,33.97 ; 85.6,78.22 P_CAL_OCP_CPU_B_0_N.2 ; P_CAL_OCP_CPU_B_0_N.2 86.73,77.09 ; P_CAL_OCP_CPU_B_0_N.2 86.73,78.22 ; P_CAL_OCP_CPU_B_0_N.2 85.6,77.09 ; P_SMA_BOT_5IN_DN_2.4 124.63,51.8 ; P_SMA_BOT_5IN_DN_2.4 124.63,52.93 ; P_SMA_BOT_5IN_DN_2.4 123.51,51.8 ; P_SMA_BOT_5IN_DN_2.4 123.51,52.93 ; 241.89,48.45 P_SMA_BOT_2IN_DP_1.2 ; P_SMA_BOT_2IN_DP_1.2 243.01,49.58 ; P_SMA_BOT_2IN_DP_1.2 243.01,48.45 ; P_SMA_BOT_2IN_DP_1.2 241.89,49.58 ; 157.29,51.98 P_SMA_TOP_5IN_DP_1.2 ; P_SMA_TOP_5IN_DP_1.2 158.41,50.85 ; P_SMA_TOP_5IN_DP_1.2 158.41,51.98 ; P_SMA_TOP_5IN_DP_1.2 157.29,50.85 ; P_SMA_BOT_2IN_DP_1.3 243.01,51.8 ; P_SMA_BOT_2IN_DP_1.3 241.89,51.8 ; P_SMA_BOT_2IN_DP_1.3 241.89,52.93 ; P_SMA_BOT_2IN_DP_1.3 243.01,52.93 ; P_SMA_BOT_5IN_DN_2.2 120.33,48.45 ; P_SMA_BOT_5IN_DN_2.2 120.33,49.58 ; P_SMA_BOT_5IN_DN_2.2 119.21,49.58 ; P_SMA_BOT_5IN_DN_2.2 119.21,48.45 ; 70.29,47.5 P_SMA_TOP_2IN_DN_2.3 ; P_SMA_TOP_2IN_DN_2.3 70.29,48.63 ; P_SMA_TOP_2IN_DN_2.3 71.42,48.63 ; P_SMA_TOP_2IN_DN_2.3 71.42,47.5 ; 120.35,77.09 P_CAL_CPU_OCP_0_N1.3 ; P_CAL_CPU_OCP_0_N1.3 121.48,78.22 ; P_CAL_CPU_OCP_0_N1.3 120.35,78.22 ; P_CAL_CPU_OCP_0_N1.3 121.48,77.09 ; 210.5,51.8 P_SMA_BOT_2IN_DP_2.4 ; P_SMA_BOT_2IN_DP_2.4 211.63,51.8 ; P_SMA_BOT_2IN_DP_2.4 211.63,52.93 ; P_SMA_BOT_2IN_DP_2.4 210.5,52.93 ; P_SMA_BOT_10IN_DP_2.3 15.41,4.07 ; P_SMA_BOT_10IN_DP_2.3 15.41,5.19 ; P_SMA_BOT_10IN_DP_2.3 14.29,4.07 ; P_SMA_BOT_10IN_DP_2.3 14.29,5.19 ; P_SMA_TOP_2IN_DN_2.2 71.42,50.85 ; P_SMA_TOP_2IN_DN_2.2 70.29,51.98 ; P_SMA_TOP_2IN_DN_2.2 71.42,51.98 ; P_SMA_TOP_2IN_DN_2.2 70.29,50.85 ; 9.99,48.45 P_SMA_BOT_5IN_DN_1.2 ; P_SMA_BOT_5IN_DN_1.2 11.11,49.58 ; P_SMA_BOT_5IN_DN_1.2 11.11,48.45 ; P_SMA_BOT_5IN_DN_1.2 9.99,49.58 ; 97.98,78.22 P_CAL_OCP_CPU_B_0_P.4 ; P_CAL_OCP_CPU_B_0_P.4 97.98,77.09 ; P_CAL_OCP_CPU_B_0_P.4 99.11,78.22 ; P_CAL_OCP_CPU_B_0_P.4 99.11,77.09 ; 123.51,48.45 P_SMA_BOT_5IN_DN_2.5 ; P_SMA_BOT_5IN_DN_2.5 123.51,49.58 ; P_SMA_BOT_5IN_DN_2.5 124.63,49.58 ; P_SMA_BOT_5IN_DN_2.5 124.63,48.45 ; 14.29,36.37 P_SMA_BOT_5IN_DP_1.2 ; P_SMA_BOT_5IN_DP_1.2 14.29,37.5 ; P_SMA_BOT_5IN_DP_1.2 15.41,37.5 ; P_SMA_BOT_5IN_DP_1.2 15.41,36.37 ; P_SMA_TOP_10IN_DP_1.2 35.73,23.02 ; P_SMA_TOP_10IN_DP_1.2 35.73,21.89 ; P_SMA_TOP_10IN_DP_1.2 34.61,21.89 ; P_SMA_TOP_10IN_DP_1.2 34.61,23.02 ; 14.29,49.58 P_SMA_BOT_5IN_DN_1.5 ; P_SMA_BOT_5IN_DN_1.5 15.41,49.58 ; P_SMA_BOT_5IN_DN_1.5 14.29,48.45 ; P_SMA_BOT_5IN_DN_1.5 15.41,48.45 ; 246.19,22.84 P_SMA_BOT_10IN_DN_1.4 ; P_SMA_BOT_10IN_DN_1.4 247.31,22.84 ; P_SMA_BOT_10IN_DN_1.4 247.31,23.97 ; P_SMA_BOT_10IN_DN_1.4 246.19,23.97 ; 119.21,34.15 P_SMA_BOT_5IN_DP_2.4 ; P_SMA_BOT_5IN_DP_2.4 119.21,33.02 ; P_SMA_BOT_5IN_DP_2.4 120.33,34.15 ; P_SMA_BOT_5IN_DP_2.4 120.33,33.02 ; 246.19,20.62 P_SMA_BOT_10IN_DN_1.5 ; P_SMA_BOT_10IN_DN_1.5 247.31,19.49 ; P_SMA_BOT_10IN_DN_1.5 246.19,19.49 ; P_SMA_BOT_10IN_DN_1.5 247.31,20.62 ; P_SMA_TOP_10IN_DP_1.3 35.73,18.54 ; P_SMA_TOP_10IN_DP_1.3 34.61,19.67 ; P_SMA_TOP_10IN_DP_1.3 35.73,19.67 ; P_SMA_TOP_10IN_DP_1.3 34.61,18.54 ; 30.31,37.32 P_SMA_TOP_10IN_DN_1.3 ; P_SMA_TOP_10IN_DN_1.3 31.43,38.45 ; P_SMA_TOP_10IN_DN_1.3 30.31,38.45 ; P_SMA_TOP_10IN_DN_1.3 31.43,37.32 ; 9.99,22.84 P_SMA_BOT_10IN_DN_2.3 ; P_SMA_BOT_10IN_DN_2.3 11.11,23.97 ; P_SMA_BOT_10IN_DN_2.3 9.99,23.97 ; P_SMA_BOT_10IN_DN_2.3 11.11,22.84 ; P_SMA_BOT_10IN_DN_1.3 243.01,22.84 ; P_SMA_BOT_10IN_DN_1.3 241.89,22.84 ; P_SMA_BOT_10IN_DN_1.3 243.01,23.97 ; P_SMA_BOT_10IN_DN_1.3 241.89,23.97 ; 262.21,37.32 P_SMA_TOP_10IN_DN_2.3 ; P_SMA_TOP_10IN_DN_2.3 263.33,37.32 ; P_SMA_TOP_10IN_DN_2.3 262.21,38.45 ; P_SMA_TOP_10IN_DN_2.3 263.33,38.45 ; P_SMA_BOT_10IN_DP_2.4 11.11,4.07 ; P_SMA_BOT_10IN_DP_2.4 9.99,4.07 ; P_SMA_BOT_10IN_DP_2.4 9.99,5.19 ; P_SMA_BOT_10IN_DP_2.4 11.11,5.19 ; 246.19,37.5 P_SMA_BOT_2IN_DN_2.2 ; P_SMA_BOT_2IN_DN_2.2 247.31,37.5 ; P_SMA_BOT_2IN_DN_2.2 246.19,36.37 ; P_SMA_BOT_2IN_DN_2.2 247.31,36.37 ; 262.21,50.85 P_SMA_TOP_5IN_DP_2.5 ; P_SMA_TOP_5IN_DP_2.5 263.33,50.85 ; P_SMA_TOP_5IN_DP_2.5 263.33,51.98 ; P_SMA_TOP_5IN_DP_2.5 262.21,51.98 ; P_SMA_TOP_2IN_DN_2.4 67.12,48.63 ; P_SMA_TOP_2IN_DN_2.4 65.99,48.63 ; P_SMA_TOP_2IN_DN_2.4 67.12,47.5 ; P_SMA_TOP_2IN_DN_2.4 65.99,47.5 ; P_CAL_CPU_OCP_0_P1.5 133.86,78.22 ; P_CAL_CPU_OCP_0_P1.5 132.73,78.22 ; P_CAL_CPU_OCP_0_P1.5 133.86,77.09 ; P_CAL_CPU_OCP_0_P1.5 132.73,77.09 ; P_CAL_CPU_OCP_0_P1.3 137.21,82.52 ; P_CAL_CPU_OCP_0_P1.3 136.08,81.39 ; P_CAL_CPU_OCP_0_P1.3 137.21,81.39 ; P_CAL_CPU_OCP_0_P1.3 136.08,82.52 ; 262.21,35.1 P_SMA_TOP_10IN_DN_2.2 ; P_SMA_TOP_10IN_DN_2.2 263.33,33.97 ; P_SMA_TOP_10IN_DN_2.2 263.33,35.1 ; P_SMA_TOP_10IN_DN_2.2 262.21,33.97 ; P_SMA_BOT_2IN_DP_2.3 207.33,51.8 ; P_SMA_BOT_2IN_DP_2.3 207.33,52.93 ; P_SMA_BOT_2IN_DP_2.3 206.2,52.93 ; P_SMA_BOT_2IN_DP_2.3 206.2,51.8 ; 9.99,36.37 P_SMA_BOT_5IN_DP_1.5 ; P_SMA_BOT_5IN_DP_1.5 11.11,36.37 ; P_SMA_BOT_5IN_DP_1.5 11.11,37.5 ; P_SMA_BOT_5IN_DP_1.5 9.99,37.5 ; 30.31,21.89 P_SMA_TOP_10IN_DP_1.5 ; P_SMA_TOP_10IN_DP_1.5 30.31,23.02 ; P_SMA_TOP_10IN_DP_1.5 31.43,21.89 ; P_SMA_TOP_10IN_DP_1.5 31.43,23.02 ; 157.29,64.05 P_SMA_TOP_5IN_DN_1.5 ; P_SMA_TOP_5IN_DN_1.5 158.41,64.05 ; P_SMA_TOP_5IN_DN_1.5 158.41,62.93 ; P_SMA_TOP_5IN_DN_1.5 157.29,62.93 ; 241.89,19.49 P_SMA_BOT_10IN_DN_1.2 ; P_SMA_BOT_10IN_DN_1.2 243.01,19.49 ; P_SMA_BOT_10IN_DN_1.2 241.89,20.62 ; P_SMA_BOT_10IN_DN_1.2 243.01,20.62 ; 262.21,18.54 P_SMA_TOP_10IN_DP_2.4 ; P_SMA_TOP_10IN_DP_2.4 263.33,19.67 ; P_SMA_TOP_10IN_DP_2.4 262.21,19.67 ; P_SMA_TOP_10IN_DP_2.4 263.33,18.54 ; 94.63,78.22 P_CAL_OCP_CPU_B_0_P.5 ; P_CAL_OCP_CPU_B_0_P.5 95.76,77.09 ; P_CAL_OCP_CPU_B_0_P.5 95.76,78.22 ; P_CAL_OCP_CPU_B_0_P.5 94.63,77.09 ; 123.7,78.22 P_CAL_CPU_OCP_0_N1.2 ; P_CAL_CPU_OCP_0_N1.2 124.83,77.09 ; P_CAL_CPU_OCP_0_N1.2 123.7,77.09 ; P_CAL_CPU_OCP_0_N1.2 124.83,78.22 ; P_CAL_OCP_CPU_B_0_N.3 83.38,78.22 ; P_CAL_OCP_CPU_B_0_N.3 83.38,77.09 ; P_CAL_OCP_CPU_B_0_N.3 82.25,77.09 ; P_CAL_OCP_CPU_B_0_N.3 82.25,78.22 ; P_SMA_TOP_5IN_DN_2.4 267.63,66.28 ; P_SMA_TOP_5IN_DN_2.4 267.63,67.4 ; P_SMA_TOP_5IN_DN_2.4 266.51,67.4 ; P_SMA_TOP_5IN_DN_2.4 266.51,66.28 ; P_SMA_TOP_2IN_DP_1.4 35.73,67.4 ; P_SMA_TOP_2IN_DP_1.4 34.61,66.28 ; P_SMA_TOP_2IN_DP_1.4 35.73,66.28 ; P_SMA_TOP_2IN_DP_1.4 34.61,67.4 ; 119.21,37.5 P_SMA_BOT_5IN_DP_2.5 ; P_SMA_BOT_5IN_DP_2.5 120.33,36.37 ; P_SMA_BOT_5IN_DP_2.5 120.33,37.5 ; P_SMA_BOT_5IN_DP_2.5 119.21,36.37 ; P_SMA_TOP_5IN_DP_2.4 263.33,48.63 ; P_SMA_TOP_5IN_DP_2.4 262.21,48.63 ; P_SMA_TOP_5IN_DP_2.4 262.21,47.5 ; P_SMA_TOP_5IN_DP_2.4 263.33,47.5 ; P_SMA_BOT_2IN_DN_2.5 243.01,36.37 ; P_SMA_BOT_2IN_DN_2.5 241.89,37.5 ; P_SMA_BOT_2IN_DN_2.5 243.01,37.5 ; P_SMA_BOT_2IN_DN_2.5 241.89,36.37 ; 262.21,67.4 P_SMA_TOP_5IN_DN_2.3 ; P_SMA_TOP_5IN_DN_2.3 263.33,66.28 ; P_SMA_TOP_5IN_DN_2.3 262.21,66.28 ; P_SMA_TOP_5IN_DN_2.3 263.33,67.4 ; 65.99,64.05 P_SMA_TOP_2IN_DP_2.2 ; P_SMA_TOP_2IN_DP_2.2 65.99,62.93 ; P_SMA_TOP_2IN_DP_2.2 67.12,64.05 ; P_SMA_TOP_2IN_DP_2.2 67.12,62.93 ; P_CAL_OCP_CPU_B_0_P.2 95.76,82.52 ; P_CAL_OCP_CPU_B_0_P.2 94.63,82.52 ; P_CAL_OCP_CPU_B_0_P.2 94.63,81.39 ; P_CAL_OCP_CPU_B_0_P.2 95.76,81.39 ; 65.99,50.85 P_SMA_TOP_2IN_DN_2.5 ; P_SMA_TOP_2IN_DN_2.5 67.12,50.85 ; P_SMA_TOP_2IN_DN_2.5 65.99,51.98 ; P_SMA_TOP_2IN_DN_2.5 67.12,51.98 ; 9.99,8.54 P_SMA_BOT_10IN_DP_2.5 ; P_SMA_BOT_10IN_DP_2.5 11.11,8.54 ; P_SMA_BOT_10IN_DP_2.5 11.11,7.42 ; P_SMA_BOT_10IN_DP_2.5 9.99,7.42 ; 70.29,67.4 P_SMA_TOP_2IN_DP_2.4 ; P_SMA_TOP_2IN_DP_2.4 70.29,66.28 ; P_SMA_TOP_2IN_DP_2.4 71.42,66.28 ; P_SMA_TOP_2IN_DP_2.4 71.42,67.4 ; 30.31,51.98 P_SMA_TOP_2IN_DN_1.5 ; P_SMA_TOP_2IN_DN_1.5 31.43,51.98 ; P_SMA_TOP_2IN_DN_1.5 31.43,50.85 ; P_SMA_TOP_2IN_DN_1.5 30.31,50.85 ; 14.29,19.49 P_SMA_BOT_10IN_DN_2.5 ; P_SMA_BOT_10IN_DN_2.5 15.41,20.62 ; P_SMA_BOT_10IN_DN_2.5 15.41,19.49 ; P_SMA_BOT_10IN_DN_2.5 14.29,20.62 ; P_SMA_BOT_2IN_DN_1.4 207.33,34.15 ; P_SMA_BOT_2IN_DN_1.4 206.2,34.15 ; P_SMA_BOT_2IN_DN_1.4 207.33,33.02 ; P_SMA_BOT_2IN_DN_1.4 206.2,33.02 ; 246.19,33.02 P_SMA_BOT_2IN_DN_2.3 ; P_SMA_BOT_2IN_DN_2.3 246.19,34.15 ; P_SMA_BOT_2IN_DN_2.3 247.31,33.02 ; P_SMA_BOT_2IN_DN_2.3 247.31,34.15 ; P_SMA_TOP_5IN_DN_2.2 263.33,62.93 ; P_SMA_TOP_5IN_DN_2.2 262.21,64.05 ; P_SMA_TOP_5IN_DN_2.2 263.33,64.05 ; P_SMA_TOP_5IN_DN_2.2 262.21,62.93
  BOTTOM w0.356: P_OCPSTRDL.A67 v1(145.3,95.81) ; P_OCPSTRDL.A43 v1(130.9,95.81) ; P_OCPSTRDL.A19 v1(108.78,96.64) v1(108.78,95.81) ; P_OCPSTRDL.A55 v1(138.1,95.81) ; P_OCPSTRDL.A58 v1(139.9,95.81) ; P_OCPSTRDL.A46 v1(132.7,95.81) ; P_OCPSTRDL.A25 v1(112.38,95.81) ; P_OCPSTRDL.A35 v1(121.79,95.81) ; P_OCPSTRDL.OCP_A6 v1(88.78,95.81) ; P_OCPSTRDL.A29 v1(118.19,95.81) ; P_OCPSTRDL.A28 v1(114.18,95.81) ; P_OCPSTRDL.A22 v1(110.58,95.81) ; P_OCPSTRDL.A32 v1(119.99,95.81) ; P_OCPSTRDL.A64 v1(143.5,95.81) ; P_OCPSTRDL.A38 v1(123.59,95.81) ; P_OCPSTRDL.A52 v1(136.3,95.81) ; P_OCPSTRDL.A49 v1(134.5,95.81) ; P_OCPSTRDL.OCP_A10 v1(91.18,95.81) ; P_OCPSTRDL.OCP_A13 v1(92.98,95.81) ; P_OCPSTRDL.A16 v1(106.98,96.64) v1(106.98,95.81) ; P_OCPSTRDL.A13 v1(105.18,95.81) ; P_OCPSTRDL.A41 v1(125.39,95.81) ; P_OCPSTRDL.A61 v1(141.7,95.81)
  vias: v1(98.11,95.38) v1(99,95.38) v1(99.89,95.38) v1(100.78,95.38) v1(106.98,97.53) v1(108.78,97.53) v2(32.27,64.69) v2(32.27,50.21) v2(32.27,35.73) v2(32.27,21.26) v2(32.37,65.07) v2(32.37,64.32) v2(32.37,50.59) v2(32.37,49.84) v2(32.37,36.11) v2(32.37,35.36) v2(32.37,21.63) v2(32.37,20.88) v2(32.65,65.34) v2(32.65,49.56) v2(32.65,36.38) v2(32.65,20.61) v2(33.02,65.44) v2(33.02,49.46) v2(33.02,36.48) v2(33.02,20.51) v2(33.39,65.34) v2(33.39,49.56) v2(33.39,36.38) v2(33.39,20.61) v2(33.67,65.07) v2(33.67,64.32) v2(33.67,50.59) v2(33.67,49.84) v2(33.67,36.11) v2(33.67,35.36) v2(33.67,21.63) v2(33.67,20.88) v2(33.77,64.69) v2(33.77,50.21) v2(33.77,35.73) v2(33.77,21.26) v2(67.96,64.69) v2(67.96,50.21) v2(68.06,65.07) v2(68.06,64.32) v2(68.06,50.59) v2(68.06,49.84) v2(68.33,65.34) v2(68.33,49.56) v2(68.71,65.44) v2(68.71,49.46) v2(69.08,65.34) v2(69.08,49.56) v2(69.36,65.07) v2(69.36,64.32) v2(69.36,50.59) v2(69.36,49.84) v2(69.46,64.69) v2(69.46,50.21) v2(122.31,79.8) v2(122.41,80.18) v2(122.41,79.43) v2(122.69,80.45) v2(122.69,79.15) v2(123.06,80.55) v2(123.06,79.05) v2(123.44,80.45) v2(123.44,79.15) v2(134.12,80.45) v2(134.12,79.15) v2(134.49,80.55) v2(134.49,79.05) v2(134.87,80.45) v2(134.87,79.15) v2(135.14,80.18) v2(135.14,79.43) v2(135.24,79.8) v2(154.95,64.69) v2(154.95,50.21) v2(155.05,65.07) v2(155.05,64.32) v2(155.05,50.59) v2(155.05,49.84) v2(155.33,65.34) v2(155.33,49.56) v2(155.7,65.44) v2(155.7,49.46) v2(156.08,65.34) v2(156.08,49.56) v2(156.35,65.07) v2(156.35,64.32) v2(156.35,50.59) v2(156.35,49.84) v2(156.45,64.69) v2(156.45,50.21) v2(264.17,64.69) v2(264.17,50.21) v2(264.17,35.73) v2(264.17,21.26) v2(264.27,65.07) v2(264.27,64.32) v2(264.27,50.59) v2(264.27,49.84) v2(264.27,36.11) v2(264.27,35.36) v2(264.27,21.63) v2(264.27,20.88) v2(264.55,65.34) v2(264.55,49.56) v2(264.55,36.38) v2(264.55,20.61) v2(264.92,65.44) v2(264.92,49.46) v2(264.92,36.48) v2(264.92,20.51) v2(265.3,65.34) v2(265.3,49.56) v2(265.3,36.38) v2(265.3,20.61) v2(265.57,65.07) v2(265.57,64.32) v2(265.57,50.59) v2(265.57,49.84) v2(265.57,36.11) v2(265.57,35.36) v2(265.57,21.63) v2(265.57,20.88) v2(265.67,64.69) v2(265.67,50.21) v2(265.67,35.73) v2(265.67,21.26) v3(12,50.21) v3(12,35.73) v3(12,21.26) v3(12,6.78) v3(12.1,50.56) v3(12.1,49.86) v3(12.1,36.08) v3(12.1,35.39) v3(12.1,21.61) v3(12.1,20.91) v3(12.1,7.13) v3(12.1,6.43) v3(12.35,50.82) v3(12.35,35.13) v3(12.35,21.86) v3(12.35,6.17) v3(12.7,50.91) v3(12.7,35.04) v3(12.7,21.96) v3(12.7,6.08) v3(13.05,50.82) v3(13.05,35.13) v3(13.05,21.86) v3(13.05,6.17) v3(13.3,50.56) v3(13.3,49.86) v3(13.3,36.08) v3(13.3,35.39) v3(13.3,21.61) v3(13.3,20.91) v3(13.3,7.13) v3(13.3,6.43) v3(13.4,50.21) v3(13.4,35.73) v3(13.4,21.26) v3(13.4,6.78) v3(84.26,79.8) v3(84.36,80.15) v3(84.36,79.45) v3(84.61,80.41) v3(84.61,79.2) v3(84.96,80.5) v3(84.96,79.11) v3(85.31,80.41) v3(85.31,79.2) v3(96.04,80.41) v3(96.04,79.2) v3(96.39,80.5) v3(96.39,79.11) v3(96.74,80.41) v3(96.74,79.2) v3(97,80.15) v3(97,79.45) v3(97.09,79.8) v3(121.22,50.21) v3(121.22,35.73) v3(121.32,50.56) v3(121.32,49.86) v3(121.32,36.08) v3(121.32,35.39) v3(121.57,50.82) v3(121.57,35.13) v3(121.92,50.91) v3(121.92,35.04) v3(122.27,50.82) v3(122.27,35.13) v3(122.52,50.56) v3(122.52,49.86) v3(122.52,36.08) v3(122.52,35.39) v3(122.62,50.21) v3(122.62,35.73) v3(208.22,50.21) v3(208.22,35.73) v3(208.31,50.56) v3(208.31,49.86) v3(208.31,36.08) v3(208.31,35.39) v3(208.57,50.82) v3(208.57,35.13) v3(208.92,50.91) v3(208.92,35.04) v3(209.26,50.82) v3(209.26,35.13) v3(209.52,50.56) v3(209.52,49.86) v3(209.52,36.08) v3(209.52,35.39) v3(209.61,50.21) v3(209.61,35.73) v3(243.9,50.21) v3(243.9,35.73) v3(243.9,21.26) v3(243.9,6.78) v3(244,50.56) v3(244,49.86) v3(244,36.08) v3(244,35.39) v3(244,21.61) v3(244,20.91) v3(244,7.13) v3(244,6.43) v3(244.25,50.82) v3(244.25,35.13) v3(244.25,21.86) v3(244.25,6.17) v3(244.6,50.91) v3(244.6,35.04) v3(244.6,21.96) v3(244.6,6.08) v3(244.95,50.82) v3(244.95,35.13) v3(244.95,21.86) v3(244.95,6.17) v3(245.21,50.56) v3(245.21,49.86) v3(245.21,36.08) v3(245.21,35.39) v3(245.21,21.61) v3(245.21,20.91) v3(245.21,7.13) v3(245.21,6.43) v3(245.3,50.21) v3(245.3,35.73) v3(245.3,21.26) v3(245.3,6.78)
